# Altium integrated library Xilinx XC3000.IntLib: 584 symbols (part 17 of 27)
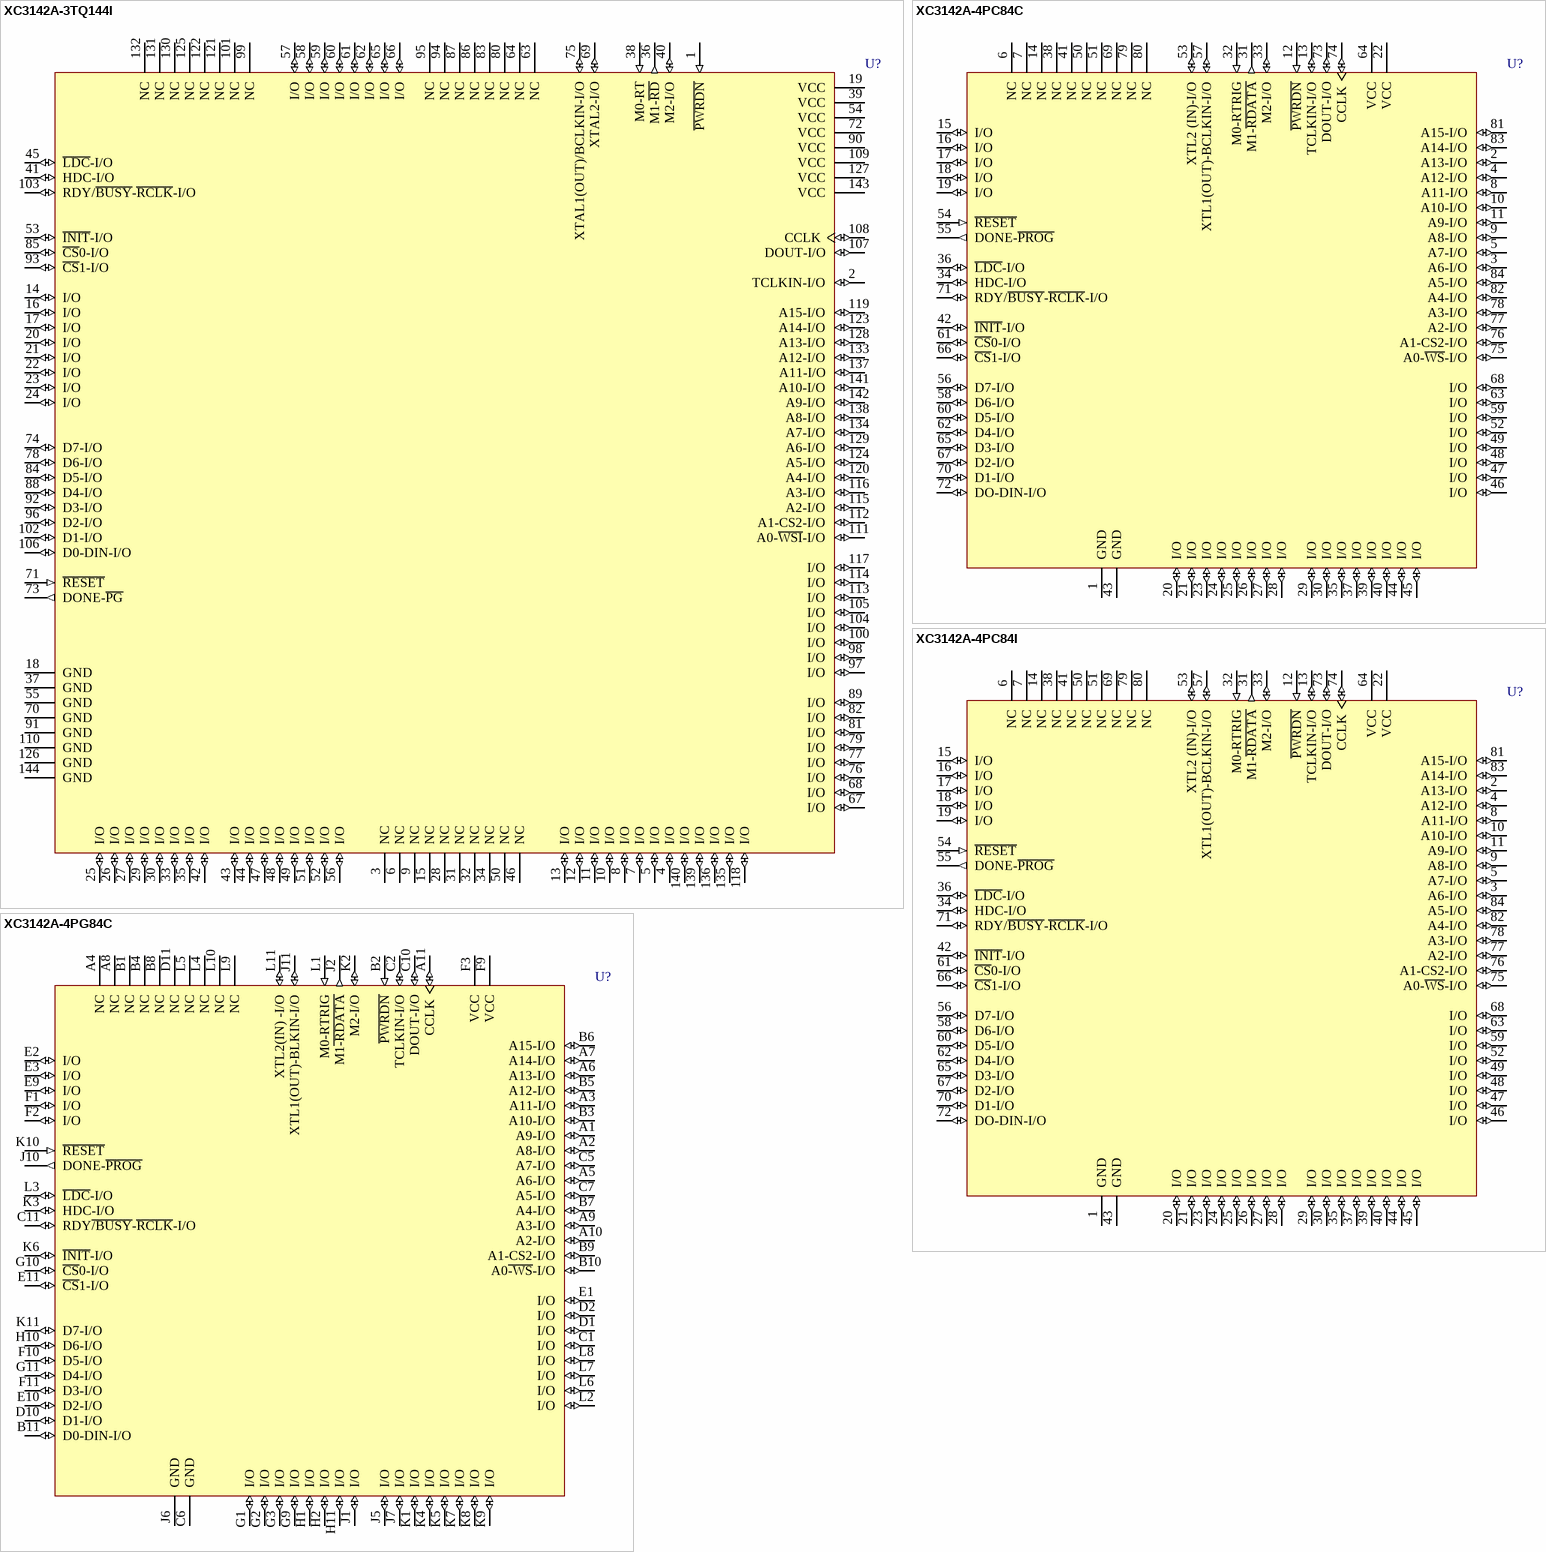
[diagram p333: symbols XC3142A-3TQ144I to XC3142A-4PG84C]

## XC3142A-3TQ144I
designator U?
Logic Cell Array with 144 CLBs, with 96 I/O Pins, 144-Pin TQFP, Industrial Grade; ComponentAvailability: Not for New Design
footprint TQ144_N (Thin QFP, 144-Leads, Body 20x20mm, Pitch 0.5mm, IPC Medium Density)
footprint TQ144_L (Thin QFP, 144-Leads, Body 20x20mm, Pitch 0.5mm, IPC High Density)
footprint TQ144_M (Thin QFP, 144-Leads, Body 20x20mm, Pitch 0.5mm, IPC Low Density)
3D model XC3142A-TQ144 (144-Pin Thin Quad Flat Pack (TQ144))
pins: 1 ~{PWRDN} (in), 2 TCLKIN-I/O (io), 3 NC, 4 I/O (io), 5 I/O (io), 6 NC, 7 I/O (io), 8 I/O (io), 9 NC, 10 I/O (io), 11 I/O (io), 12 I/O (io), 13 I/O (io), 14 I/O (io), 15 NC, 16 I/O (io), 17 I/O (io), 18 GND (power), 19 VCC (power), 20 I/O (io), 21 I/O (io), 22 I/O (io), 23 I/O (io), 24 I/O (io), 25 I/O (io), 26 I/O (io), 27 I/O (io), 28 NC, 29 I/O (io), 30 I/O (io), 31 NC, 32 NC, 33 I/O (io), 34 NC, 35 I/O (io), 36 M1-~{RD} (out), 37 GND (power), 38 M0-RT (in), 39 VCC (power), 40 M2-I/O (io), 41 HDC-I/O (io), 42 I/O (io), 43 I/O (io), 44 I/O (io), 45 ~{LDC}-I/O (io), 46 NC, 47 I/O (io), 48 I/O (io), 49 I/O (io), 50 NC, 51 I/O (io), 52 I/O (io), 53 ~{INIT}-I/O (io), 54 VCC (power), 55 GND (power), 56 I/O (io), 57 I/O (io), 58 I/O (io), 59 I/O (io), 60 I/O (io), 61 I/O (io), 62 I/O (io), 63 NC, 64 NC, 65 I/O (io), 66 I/O (io), 67 I/O (io), 68 I/O (io), 69 XTAL2-I/O (io), 70 GND (power), 71 ~{RESET} (in), 72 VCC (power), 73 DONE-~{PG} (out), 74 D7-I/O (io), 75 XTAL1(OUT)/BCLKIN-I/O (io), 76 I/O (io), 77 I/O (io), 78 D6-I/O (io), 79 I/O (io), 80 NC, 81 I/O (io), 82 I/O (io), 83 NC, 84 D5-I/O (io), 85 ~{CS}0-I/O (io), 86 NC, 87 NC, 88 D4-I/O (io), 89 I/O (io), 90 VCC (power), 91 GND (power), 92 D3-I/O (io), 93 ~{CS}1-I/O (io), 94 NC, 95 NC, 96 D2-I/O (io), 97 I/O (io), 98 I/O (io), 99 NC, 100 I/O (io), 101 NC, 102 D1-I/O (io), 103 RDY/~{BUSY}-~{RCLK}-I/O (io), 104 I/O (io), 105 I/O (io), 106 D0-DIN-I/O (io), 107 DOUT-I/O (io), 108 CCLK (io), 109 VCC (power), 110 GND (power), 111 A0-~{WSI}-I/O (io), 112 A1-CS2-I/O (io), 113 I/O (io), 114 I/O (io), 115 A2-I/O (io), 116 A3-I/O (io), 117 I/O (io), 118 I/O (io), 119 A15-I/O (io), 120 A4-I/O (io), 121 NC, 122 NC, 123 A14-I/O (io), 124 A5-I/O (io), 125 NC, 126 GND (power), 127 VCC (power), 128 A13-I/O (io), 129 A6-I/O (io), 130 NC, 131 NC, 132 NC, 133 A12-I/O (io), 134 A7-I/O (io), 135 I/O (io), 136 I/O (io), 137 A11-I/O (io), 138 A8-I/O (io), 139 I/O (io), 140 I/O (io), 141 A10-I/O (io), 142 A9-I/O (io), 143 VCC (power), 144 GND (power)

## XC3142A-4PC84C
designator U?
Logic Cell Array with 144 CLBs, with 64 I/O Pins, 84-Pin PLCC, Commercial Grade; ComponentAvailability: Not for New Design
footprint PC84_N (Leaded Chip Carrier, 84-Leads, Body 29.3x29.3mm, Pitch 1.27mm, IPC Medium Density)
footprint PC84_L (Leaded Chip Carrier, 84-Leads, Body 29.3x29.3mm, Pitch 1.27mm, IPC High Density)
footprint PC84_M (Leaded Chip Carrier, 84-Leads, Body 29.3x29.3mm, Pitch 1.27mm, IPC Low Density)
3D model XC3142A-PC84 (84-Pin Plastic Leaded Chip Carrier (PC84))
pins: 1 GND (power), 2 A13-I/O (io), 3 A6-I/O (io), 4 A12-I/O (io), 5 A7-I/O (io), 6 NC, 7 NC, 8 A11-I/O (io), 9 A8-I/O (io), 10 A10-I/O (io), 11 A9-I/O (io), 12 ~{PWRDN} (in), 13 TCLKIN-I/O (io), 14 NC, 15 I/O (io), 16 I/O (io), 17 I/O (io), 18 I/O (io), 19 I/O (io), 20 I/O (io), 21 I/O (io), 22 VCC (power), 23 I/O (io), 24 I/O (io), 25 I/O (io), 26 I/O (io), 27 I/O (io), 28 I/O (io), 29 I/O (io), 30 I/O (io), 31 M1-~{RDATA} (out), 32 M0-RTRIG (in), 33 M2-I/O (io), 34 HDC-I/O (io), 35 I/O (io), 36 ~{LDC}-I/O (io), 37 I/O (io), 38 NC, 39 I/O (io), 40 I/O (io), 41 NC, 42 ~{INIT}-I/O (io), 43 GND (power), 44 I/O (io), 45 I/O (io), 46 I/O (io), 47 I/O (io), 48 I/O (io), 49 I/O (io), 50 NC, 51 NC, 52 I/O (io), 53 XTL2 (IN)-I/O (io), 54 ~{RESET} (in), 55 DONE-~{PROG} (out), 56 D7-I/O (io), 57 XTL1(OUT)-BCLKIN-I/O (io), 58 D6-I/O (io), 59 I/O (io), 60 D5-I/O (io), 61 ~{CS}0-I/O (io), 62 D4-I/O (io), 63 I/O (io), 64 VCC (power), 65 D3-I/O (io), 66 ~{CS}1-I/O (io), 67 D2-I/O (io), 68 I/O (io), 69 NC, 70 D1-I/O (io), 71 RDY/~{BUSY}-~{RCLK}-I/O (io), 72 DO-DIN-I/O (io), 73 DOUT-I/O (io), 74 CCLK (io), 75 A0-~{WS}-I/O (io), 76 A1-CS2-I/O (io), 77 A2-I/O (io), 78 A3-I/O (io), 79 NC, 80 NC, 81 A15-I/O (io), 82 A4-I/O (io), 83 A14-I/O (io), 84 A5-I/O (io)

## XC3142A-4PC84I
designator U?
Logic Cell Array with 144 CLBs, with 64 I/O Pins, 84-Pin PLCC, Industrial Grade; ComponentAvailability: Not for New Design
footprint PC84_N (Leaded Chip Carrier, 84-Leads, Body 29.3x29.3mm, Pitch 1.27mm, IPC Medium Density)
footprint PC84_L (Leaded Chip Carrier, 84-Leads, Body 29.3x29.3mm, Pitch 1.27mm, IPC High Density)
footprint PC84_M (Leaded Chip Carrier, 84-Leads, Body 29.3x29.3mm, Pitch 1.27mm, IPC Low Density)
3D model XC3142A-PC84 (84-Pin Plastic Leaded Chip Carrier (PC84))
pins: 1 GND (power), 2 A13-I/O (io), 3 A6-I/O (io), 4 A12-I/O (io), 5 A7-I/O (io), 6 NC, 7 NC, 8 A11-I/O (io), 9 A8-I/O (io), 10 A10-I/O (io), 11 A9-I/O (io), 12 ~{PWRDN} (in), 13 TCLKIN-I/O (io), 14 NC, 15 I/O (io), 16 I/O (io), 17 I/O (io), 18 I/O (io), 19 I/O (io), 20 I/O (io), 21 I/O (io), 22 VCC (power), 23 I/O (io), 24 I/O (io), 25 I/O (io), 26 I/O (io), 27 I/O (io), 28 I/O (io), 29 I/O (io), 30 I/O (io), 31 M1-~{RDATA} (out), 32 M0-RTRIG (in), 33 M2-I/O (io), 34 HDC-I/O (io), 35 I/O (io), 36 ~{LDC}-I/O (io), 37 I/O (io), 38 NC, 39 I/O (io), 40 I/O (io), 41 NC, 42 ~{INIT}-I/O (io), 43 GND (power), 44 I/O (io), 45 I/O (io), 46 I/O (io), 47 I/O (io), 48 I/O (io), 49 I/O (io), 50 NC, 51 NC, 52 I/O (io), 53 XTL2 (IN)-I/O (io), 54 ~{RESET} (in), 55 DONE-~{PROG} (out), 56 D7-I/O (io), 57 XTL1(OUT)-BCLKIN-I/O (io), 58 D6-I/O (io), 59 I/O (io), 60 D5-I/O (io), 61 ~{CS}0-I/O (io), 62 D4-I/O (io), 63 I/O (io), 64 VCC (power), 65 D3-I/O (io), 66 ~{CS}1-I/O (io), 67 D2-I/O (io), 68 I/O (io), 69 NC, 70 D1-I/O (io), 71 RDY/~{BUSY}-~{RCLK}-I/O (io), 72 DO-DIN-I/O (io), 73 DOUT-I/O (io), 74 CCLK (io), 75 A0-~{WS}-I/O (io), 76 A1-CS2-I/O (io), 77 A2-I/O (io), 78 A3-I/O (io), 79 NC, 80 NC, 81 A15-I/O (io), 82 A4-I/O (io), 83 A14-I/O (io), 84 A5-I/O (io)

## XC3142A-4PG84C
designator U?
Logic Cell Array with 144 CLBs, with 64 I/O Pins, 84-Pin PGA, Commercial Grade; ComponentAvailability: Not for New Design
footprint PG84 (PGA, 85-Leads, Body 28x28mm, Pitch 2.54mm)
3D model XC3142A-PG84 (84-Pin Ceramic Pin Grid Array (PG84))
pins: A1 A9-I/O (io), A2 A8-I/O (io), A3 A11-I/O (io), A4 NC, A5 A6-I/O (io), A6 A13-I/O (io), A7 A14-I/O (io), A8 NC, A9 A3-I/O (io), A10 A2-I/O (io), A11 CCLK (io), B1 NC, B2 ~{PWRDN} (in), B3 A10-I/O (io), B4 NC, B5 A12-I/O (io), B6 A15-I/O (io), B7 A4-I/O (io), B8 NC, B9 A1-CS2-I/O (io), B10 A0~{-WS}-I/O (io), B11 D0-DIN-I/O (io), C1 I/O (io), C2 TCLKIN-I/O (io), C5 A7-I/O (io), C6 GND (power), C7 A5-I/O (io), C10 DOUT-I/O (io), C11 RDY~{/BUSY}-~{RCLK}-I/O (io), D1 I/O (io), D2 I/O (io), D10 D1-I/O (io), D11 NC, E1 I/O (io), E2 I/O (io), E3 I/O (io), E9 I/O (io), E10 D2-I/O (io), E11 ~{CS}1-I/O (io), F1 I/O (io), F2 I/O (io), F3 VCC (power), F9 VCC (power), F10 D5-I/O (io), F11 D3-I/O (io), G1 I/O (io), G2 I/O (io), G3 I/O (io), G9 I/O (io), G10 ~{CS}0-I/O (io), G11 D4-I/O (io), H1 I/O (io), H2 I/O (io), H10 D6-I/O (io), H11 I/O (io), J1 I/O (io), J2 M1~{-RDATA} (out), J5 I/O (io), J6 GND (power), J7 I/O (io), J10 DONE-~{PROG} (out), J11 XTL1(OUT)-BLKIN-I/O (io), K1 I/O (io), K2 M2-I/O (io), K3 HDC-I/O (io), K4 I/O (io), K5 I/O (io), K6 ~{INIT}-I/O (io), K7 I/O (io), K8 I/O (io), K9 I/O (io), K10 ~{RESET} (in), K11 D7-I/O (io), L1 M0-RTRIG (in), L2 I/O (io), L3 ~{LDC}-I/O (io), L4 NC, L5 NC, L6 I/O (io), L7 I/O (io), L8 I/O (io), L9 NC, L10 NC, L11 XTL2(IN) -I/O (io)

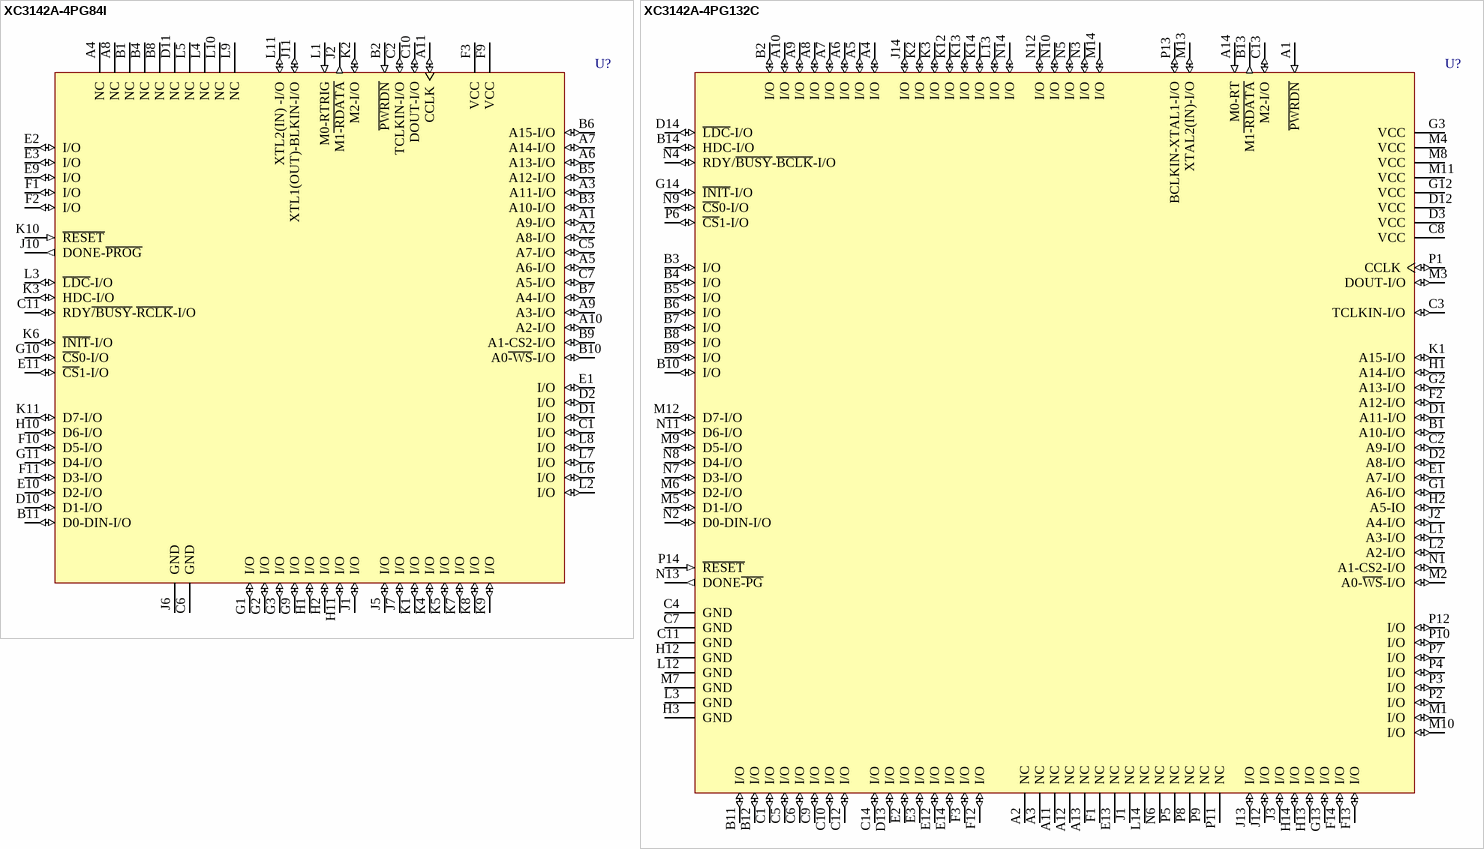
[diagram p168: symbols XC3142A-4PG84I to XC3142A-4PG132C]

## XC3142A-4PG84I
designator U?
Logic Cell Array with 144 CLBs, with 64 I/O Pins, 84-Pin PGA, Industrial Grade; ComponentAvailability: Not for New Design
footprint PG84 (PGA, 85-Leads, Body 28x28mm, Pitch 2.54mm)
3D model XC3142A-PG84 (84-Pin Ceramic Pin Grid Array (PG84))
pins: A1 A9-I/O (io), A2 A8-I/O (io), A3 A11-I/O (io), A4 NC, A5 A6-I/O (io), A6 A13-I/O (io), A7 A14-I/O (io), A8 NC, A9 A3-I/O (io), A10 A2-I/O (io), A11 CCLK (io), B1 NC, B2 ~{PWRDN} (in), B3 A10-I/O (io), B4 NC, B5 A12-I/O (io), B6 A15-I/O (io), B7 A4-I/O (io), B8 NC, B9 A1-CS2-I/O (io), B10 A0~{-WS}-I/O (io), B11 D0-DIN-I/O (io), C1 I/O (io), C2 TCLKIN-I/O (io), C5 A7-I/O (io), C6 GND (power), C7 A5-I/O (io), C10 DOUT-I/O (io), C11 RDY~{/BUSY}-~{RCLK}-I/O (io), D1 I/O (io), D2 I/O (io), D10 D1-I/O (io), D11 NC, E1 I/O (io), E2 I/O (io), E3 I/O (io), E9 I/O (io), E10 D2-I/O (io), E11 ~{CS}1-I/O (io), F1 I/O (io), F2 I/O (io), F3 VCC (power), F9 VCC (power), F10 D5-I/O (io), F11 D3-I/O (io), G1 I/O (io), G2 I/O (io), G3 I/O (io), G9 I/O (io), G10 ~{CS}0-I/O (io), G11 D4-I/O (io), H1 I/O (io), H2 I/O (io), H10 D6-I/O (io), H11 I/O (io), J1 I/O (io), J2 M1~{-RDATA} (out), J5 I/O (io), J6 GND (power), J7 I/O (io), J10 DONE-~{PROG} (out), J11 XTL1(OUT)-BLKIN-I/O (io), K1 I/O (io), K2 M2-I/O (io), K3 HDC-I/O (io), K4 I/O (io), K5 I/O (io), K6 ~{INIT}-I/O (io), K7 I/O (io), K8 I/O (io), K9 I/O (io), K10 ~{RESET} (in), K11 D7-I/O (io), L1 M0-RTRIG (in), L2 I/O (io), L3 ~{LDC}-I/O (io), L4 NC, L5 NC, L6 I/O (io), L7 I/O (io), L8 I/O (io), L9 NC, L10 NC, L11 XTL2(IN) -I/O (io)

## XC3142A-4PG132C
designator U?
Logic Cell Array with 144 CLBs, with 96 I/O Pins, 132-Pin PGA, Commercial Grade; ComponentAvailability: Not for New Design
footprint PG132 (PGA, 132-Leads, Body 37x37mm, Pitch 2.54mm)
3D model XC3142A-PG132 (132-Pin Ceramic Pin Grid Array (PG132))
pins: A1 ~{PWRDN} (in), A2 NC, A3 NC, A4 I/O (io), A5 I/O (io), A6 I/O (io), A7 I/O (io), A8 I/O (io), A9 I/O (io), A10 I/O (io), A11 NC, A12 NC, A13 NC, A14 M0-RT (in), B1 A10-I/O (io), B2 I/O (io), B3 I/O (io), B4 I/O (io), B5 I/O (io), B6 I/O (io), B7 I/O (io), B8 I/O (io), B9 I/O (io), B10 I/O (io), B11 I/O (io), B12 I/O (io), B13 M1~{-RDATA} (out), B14 HDC-I/O (io), C1 I/O (io), C2 A9-I/O (io), C3 TCLKIN-I/O (io), C4 GND (power), C5 I/O (io), C6 I/O (io), C7 GND (power), C8 VCC (power), C9 I/O (io), C10 I/O (io), C11 GND (power), C12 I/O (io), C13 M2-I/O (io), C14 I/O (io), D1 A11-I/O (io), D2 A8-I/O (io), D3 VCC (power), D12 VCC (power), D13 I/O (io), D14 ~{LDC}-I/O (io), E1 A7-I/O (io), E2 I/O (io), E3 I/O (io), E12 I/O (io), E13 NC, E14 I/O (io), F1 NC, F2 A12-I/O (io), F3 I/O (io), F12 I/O (io), F13 I/O (io), F14 I/O (io), G1 A6-I/O (io), G2 A13-I/O (io), G3 VCC (power), G12 VCC (power), G13 I/O (io), G14 ~{INIT}-I/O (io), H1 A14-I/O (io), H2 A5-IO (io), H3 GND (power), H12 GND (power), H13 I/O (io), H14 I/O (io), J1 NC, J2 A4-I/O (io), J3 I/O (io), J12 I/O (io), J13 I/O (io), J14 I/O (io), K1 A15-I/O (io), K2 I/O (io), K3 I/O (io), K12 I/O (io), K13 I/O (io), K14 I/O (io), L1 A3-I/O (io), L2 A2-I/O (io), L3 GND (power), L12 GND (power), L13 I/O (io), L14 NC, M1 I/O (io), M2 A0-~{WS}-I/O (io), M3 DOUT-I/O (io), M4 VCC (power), M5 D1-I/O (io), M6 D2-I/O (io), M7 GND (power), M8 VCC (power), M9 D5-I/O (io), M10 I/O (io), M11 VCC (power), M12 D7-I/O (io), M13 XTAL2(IN)-I/O (io), M14 I/O (io), N1 A1-CS2-I/O (io), N2 D0-DIN-I/O (io), N3 I/O (io), N4 RDY/~{BUSY}-~{BCLK}-I/O (io), N5 I/O (io), N6 NC, N7 D3-I/O (io), N8 D4-I/O (io), N9 ~{CS}0-I/O (io), N10 I/O (io), N11 D6-I/O (io), N12 I/O (io), N13 DONE~{-PG} (out), N14 I/O (io), P1 CCLK (io), P2 I/O (io), P3 I/O (io), P4 I/O (io), P5 NC, P6 ~{CS}1-I/O (io), P7 I/O (io), P8 NC, P9 NC, P10 I/O (io), P11 NC, P12 I/O (io), P13 BCLKIN-XTAL1-I/O (io), P14 ~{RESET} (in)

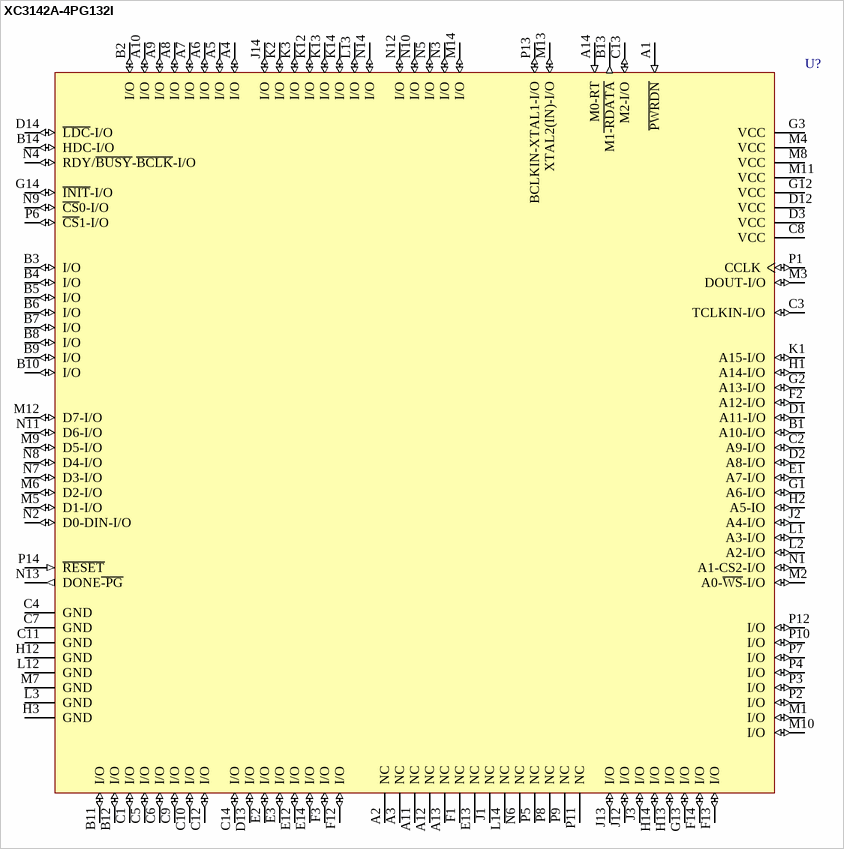
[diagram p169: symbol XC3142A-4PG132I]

## XC3142A-4PG132I
designator U?
Logic Cell Array with 144 CLBs, with 96 I/O Pins, 132-Pin PGA, Industrial Grade; ComponentAvailability: Not for New Design
footprint PG132 (PGA, 132-Leads, Body 37x37mm, Pitch 2.54mm)
3D model XC3142A-PG132 (132-Pin Ceramic Pin Grid Array (PG132))
pins: A1 ~{PWRDN} (in), A2 NC, A3 NC, A4 I/O (io), A5 I/O (io), A6 I/O (io), A7 I/O (io), A8 I/O (io), A9 I/O (io), A10 I/O (io), A11 NC, A12 NC, A13 NC, A14 M0-RT (in), B1 A10-I/O (io), B2 I/O (io), B3 I/O (io), B4 I/O (io), B5 I/O (io), B6 I/O (io), B7 I/O (io), B8 I/O (io), B9 I/O (io), B10 I/O (io), B11 I/O (io), B12 I/O (io), B13 M1~{-RDATA} (out), B14 HDC-I/O (io), C1 I/O (io), C2 A9-I/O (io), C3 TCLKIN-I/O (io), C4 GND (power), C5 I/O (io), C6 I/O (io), C7 GND (power), C8 VCC (power), C9 I/O (io), C10 I/O (io), C11 GND (power), C12 I/O (io), C13 M2-I/O (io), C14 I/O (io), D1 A11-I/O (io), D2 A8-I/O (io), D3 VCC (power), D12 VCC (power), D13 I/O (io), D14 ~{LDC}-I/O (io), E1 A7-I/O (io), E2 I/O (io), E3 I/O (io), E12 I/O (io), E13 NC, E14 I/O (io), F1 NC, F2 A12-I/O (io), F3 I/O (io), F12 I/O (io), F13 I/O (io), F14 I/O (io), G1 A6-I/O (io), G2 A13-I/O (io), G3 VCC (power), G12 VCC (power), G13 I/O (io), G14 ~{INIT}-I/O (io), H1 A14-I/O (io), H2 A5-IO (io), H3 GND (power), H12 GND (power), H13 I/O (io), H14 I/O (io), J1 NC, J2 A4-I/O (io), J3 I/O (io), J12 I/O (io), J13 I/O (io), J14 I/O (io), K1 A15-I/O (io), K2 I/O (io), K3 I/O (io), K12 I/O (io), K13 I/O (io), K14 I/O (io), L1 A3-I/O (io), L2 A2-I/O (io), L3 GND (power), L12 GND (power), L13 I/O (io), L14 NC, M1 I/O (io), M2 A0-~{WS}-I/O (io), M3 DOUT-I/O (io), M4 VCC (power), M5 D1-I/O (io), M6 D2-I/O (io), M7 GND (power), M8 VCC (power), M9 D5-I/O (io), M10 I/O (io), M11 VCC (power), M12 D7-I/O (io), M13 XTAL2(IN)-I/O (io), M14 I/O (io), N1 A1-CS2-I/O (io), N2 D0-DIN-I/O (io), N3 I/O (io), N4 RDY/~{BUSY}-~{BCLK}-I/O (io), N5 I/O (io), N6 NC, N7 D3-I/O (io), N8 D4-I/O (io), N9 ~{CS}0-I/O (io), N10 I/O (io), N11 D6-I/O (io), N12 I/O (io), N13 DONE~{-PG} (out), N14 I/O (io), P1 CCLK (io), P2 I/O (io), P3 I/O (io), P4 I/O (io), P5 NC, P6 ~{CS}1-I/O (io), P7 I/O (io), P8 NC, P9 NC, P10 I/O (io), P11 NC, P12 I/O (io), P13 BCLKIN-XTAL1-I/O (io), P14 ~{RESET} (in)

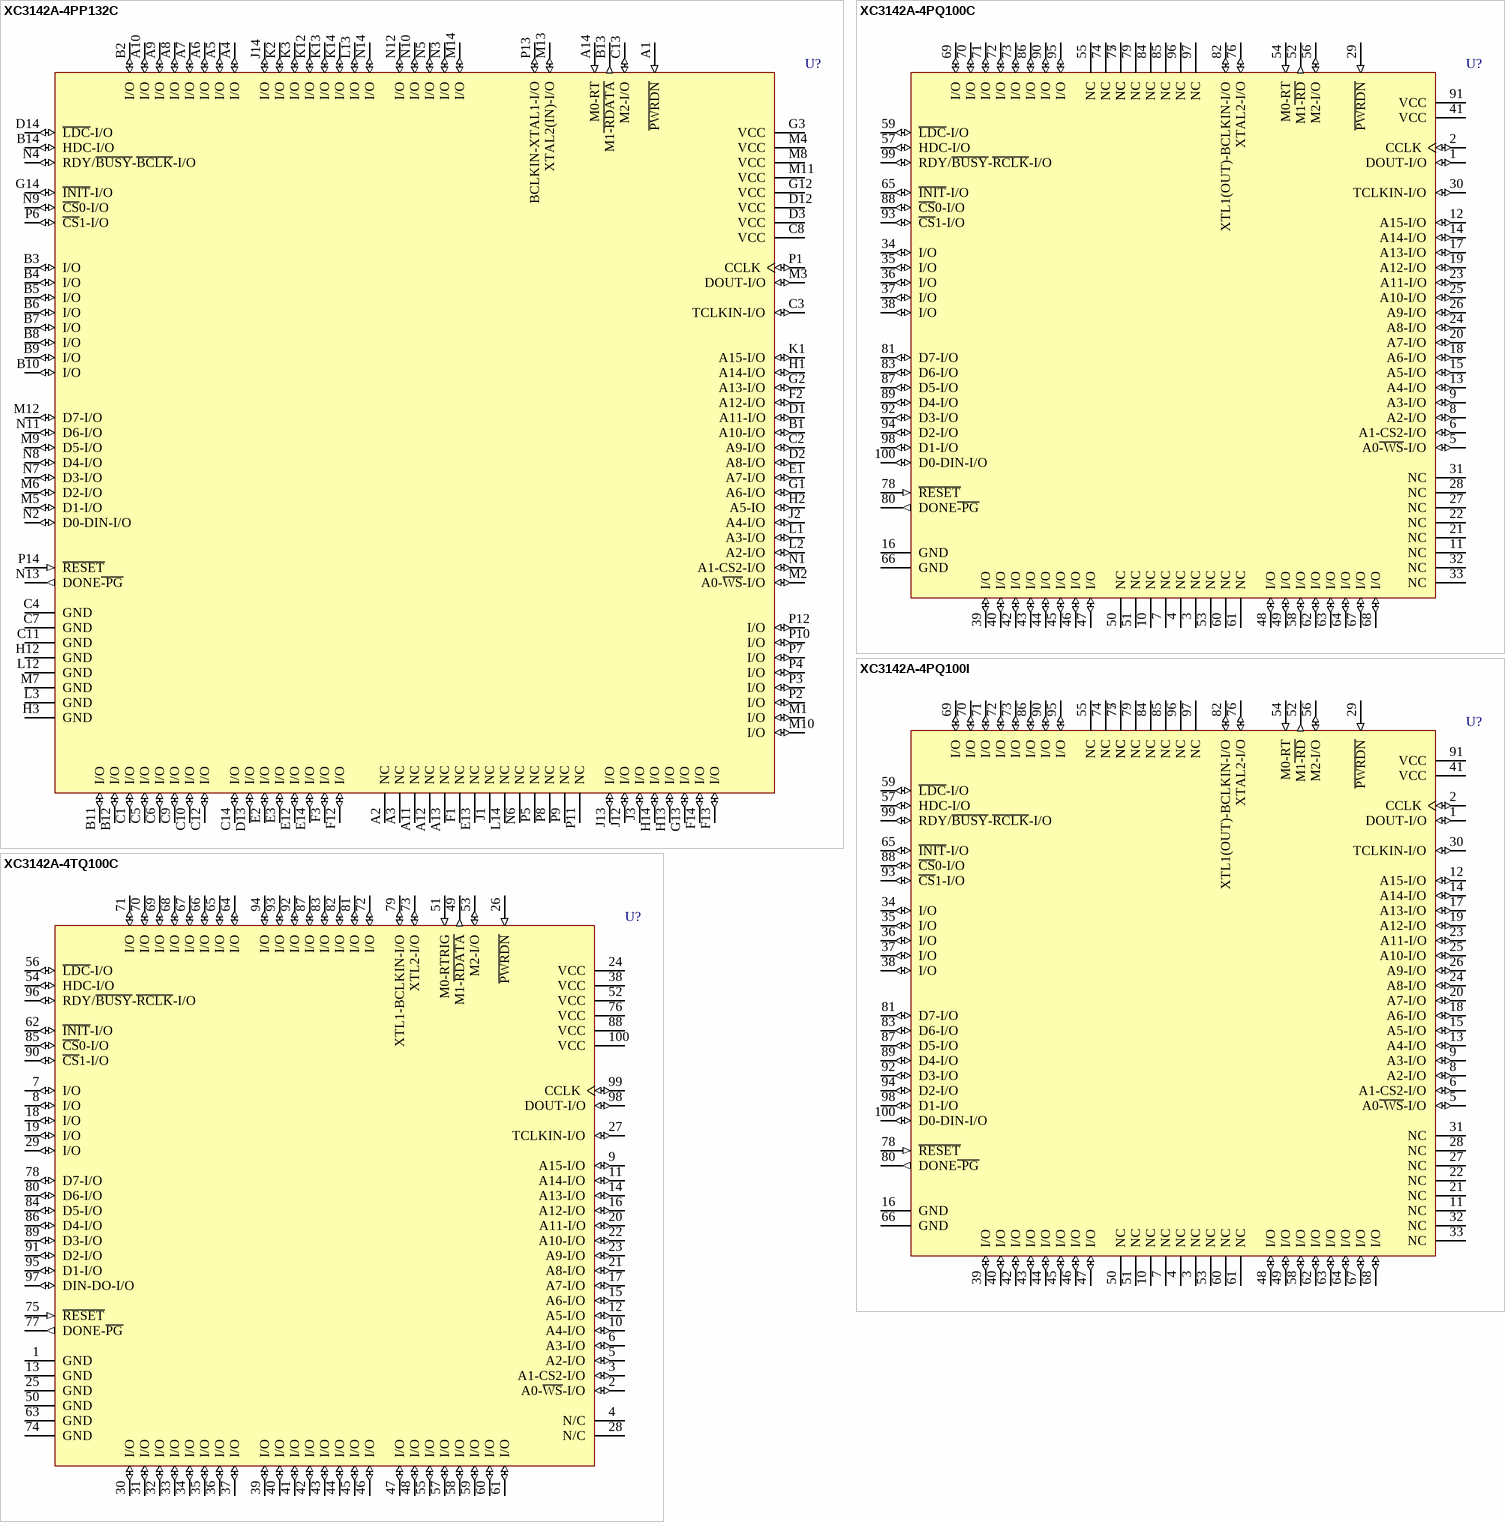
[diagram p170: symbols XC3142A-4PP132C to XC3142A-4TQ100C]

## XC3142A-4PP132C
designator U?
Logic Cell Array with 144 CLBs, with 96 I/O Pins, 132-Pin PGA, Commercial Grade; ComponentAvailability: Not for New Design
footprint PP132 (PGA, 132-Leads, Body 37x37mm, Pitch 2.54mm)
3D model XC3142A-PP132 (132-Pin Plastic Pin Grid Array (PP132))
pins: A1 ~{PWRDN} (in), A2 NC, A3 NC, A4 I/O (io), A5 I/O (io), A6 I/O (io), A7 I/O (io), A8 I/O (io), A9 I/O (io), A10 I/O (io), A11 NC, A12 NC, A13 NC, A14 M0-RT (in), B1 A10-I/O (io), B2 I/O (io), B3 I/O (io), B4 I/O (io), B5 I/O (io), B6 I/O (io), B7 I/O (io), B8 I/O (io), B9 I/O (io), B10 I/O (io), B11 I/O (io), B12 I/O (io), B13 M1~{-RDATA} (out), B14 HDC-I/O (io), C1 I/O (io), C2 A9-I/O (io), C3 TCLKIN-I/O (io), C4 GND (power), C5 I/O (io), C6 I/O (io), C7 GND (power), C8 VCC (power), C9 I/O (io), C10 I/O (io), C11 GND (power), C12 I/O (io), C13 M2-I/O (io), C14 I/O (io), D1 A11-I/O (io), D2 A8-I/O (io), D3 VCC (power), D12 VCC (power), D13 I/O (io), D14 ~{LDC}-I/O (io), E1 A7-I/O (io), E2 I/O (io), E3 I/O (io), E12 I/O (io), E13 NC, E14 I/O (io), F1 NC, F2 A12-I/O (io), F3 I/O (io), F12 I/O (io), F13 I/O (io), F14 I/O (io), G1 A6-I/O (io), G2 A13-I/O (io), G3 VCC (power), G12 VCC (power), G13 I/O (io), G14 ~{INIT}-I/O (io), H1 A14-I/O (io), H2 A5-IO (io), H3 GND (power), H12 GND (power), H13 I/O (io), H14 I/O (io), J1 NC, J2 A4-I/O (io), J3 I/O (io), J12 I/O (io), J13 I/O (io), J14 I/O (io), K1 A15-I/O (io), K2 I/O (io), K3 I/O (io), K12 I/O (io), K13 I/O (io), K14 I/O (io), L1 A3-I/O (io), L2 A2-I/O (io), L3 GND (power), L12 GND (power), L13 I/O (io), L14 NC, M1 I/O (io), M2 A0-~{WS}-I/O (io), M3 DOUT-I/O (io), M4 VCC (power), M5 D1-I/O (io), M6 D2-I/O (io), M7 GND (power), M8 VCC (power), M9 D5-I/O (io), M10 I/O (io), M11 VCC (power), M12 D7-I/O (io), M13 XTAL2(IN)-I/O (io), M14 I/O (io), N1 A1-CS2-I/O (io), N2 D0-DIN-I/O (io), N3 I/O (io), N4 RDY/~{BUSY}-~{BCLK}-I/O (io), N5 I/O (io), N6 NC, N7 D3-I/O (io), N8 D4-I/O (io), N9 ~{CS}0-I/O (io), N10 I/O (io), N11 D6-I/O (io), N12 I/O (io), N13 DONE~{-PG} (out), N14 I/O (io), P1 CCLK (io), P2 I/O (io), P3 I/O (io), P4 I/O (io), P5 NC, P6 ~{CS}1-I/O (io), P7 I/O (io), P8 NC, P9 NC, P10 I/O (io), P11 NC, P12 I/O (io), P13 BCLKIN-XTAL1-I/O (io), P14 ~{RESET} (in)

## XC3142A-4PQ100C
designator U?
Logic Cell Array with 144 CLBs, with 62 I/O Pins, 100-Pin PQFP, Commercial Grade; ComponentAvailability: Not for New Design
footprint PQ100_N (QFP, 100-Leads, Body 20x14mm, Pitch 0.65mm, IPC Medium Density)
footprint PQ100_L (QFP, 100-Leads, Body 20x14mm, Pitch 0.65mm, IPC High Density)
footprint PQ100_M (QFP, 100-Leads, Body 20x14mm, Pitch 0.65mm, IPC Low Density)
3D model XC3142A-PQ100 (100-Pin Plastic Quad Flat Pack (PQ100))
pins: 1 DOUT-I/O (io), 2 CCLK (io), 3 NC, 4 NC, 5 A0~{-WS}-I/O (io), 6 A1-CS2-I/O (io), 7 NC, 8 A2-I/O (io), 9 A3-I/O (io), 10 NC, 11 NC, 12 A15-I/O (io), 13 A4-I/O (io), 14 A14-I/O (io), 15 A5-I/O (io), 16 GND (power), 17 A13-I/O (io), 18 A6-I/O (io), 19 A12-I/O (io), 20 A7-I/O (io), 21 NC, 22 NC, 23 A11-I/O (io), 24 A8-I/O (io), 25 A10-I/O (io), 26 A9-I/O (io), 27 NC, 28 NC, 29 ~{PWRDN} (in), 30 TCLKIN-I/O (io), 31 NC, 32 NC, 33 NC, 34 I/O (io), 35 I/O (io), 36 I/O (io), 37 I/O (io), 38 I/O (io), 39 I/O (io), 40 I/O (io), 41 VCC (power), 42 I/O (io), 43 I/O (io), 44 I/O (io), 45 I/O (io), 46 I/O (io), 47 I/O (io), 48 I/O (io), 49 I/O (io), 50 NC, 51 NC, 52 M1~{-RD} (out), 53 NC, 54 M0-RT (in), 55 NC, 56 M2-I/O (io), 57 HDC-I/O (io), 58 I/O (io), 59 ~{LDC}-I/O (io), 60 NC, 61 NC, 62 I/O (io), 63 I/O (io), 64 I/O (io), 65 ~{INIT}-I/O (io), 66 GND (power), 67 I/O (io), 68 I/O (io), 69 I/O (io), 70 I/O (io), 71 I/O (io), 72 I/O (io), 73 I/O (io), 74 NC, 75 NC, 76 XTAL2-I/O (io), 77 NC, 78 ~{RESET} (in), 79 NC, 80 DONE~{-PG} (out), 81 D7-I/O (io), 82 XTL1(OUT)-BCLKIN-I/O (io), 83 D6-I/O (io), 84 NC, 85 NC, 86 I/O (io), 87 D5-I/O (io), 88 ~{CS}0-I/O (io), 89 D4-I/O (io), 90 I/O (io), 91 VCC (power), 92 D3-I/O (io), 93 ~{CS}1-I/O (io), 94 D2-I/O (io), 95 I/O (io), 96 NC, 97 NC, 98 D1-I/O (io), 99 RDY/~{BUSY}-~{RCLK}-I/O (io), 100 D0-DIN-I/O (io)

## XC3142A-4PQ100I
designator U?
Logic Cell Array with 144 CLBs, with 62 I/O Pins, 100-Pin PQFP, Industrial Grade; ComponentAvailability: Not for New Design
footprint PQ100_N (QFP, 100-Leads, Body 20x14mm, Pitch 0.65mm, IPC Medium Density)
footprint PQ100_L (QFP, 100-Leads, Body 20x14mm, Pitch 0.65mm, IPC High Density)
footprint PQ100_M (QFP, 100-Leads, Body 20x14mm, Pitch 0.65mm, IPC Low Density)
3D model XC3142A-PQ100 (100-Pin Plastic Quad Flat Pack (PQ100))
pins: 1 DOUT-I/O (io), 2 CCLK (io), 3 NC, 4 NC, 5 A0~{-WS}-I/O (io), 6 A1-CS2-I/O (io), 7 NC, 8 A2-I/O (io), 9 A3-I/O (io), 10 NC, 11 NC, 12 A15-I/O (io), 13 A4-I/O (io), 14 A14-I/O (io), 15 A5-I/O (io), 16 GND (power), 17 A13-I/O (io), 18 A6-I/O (io), 19 A12-I/O (io), 20 A7-I/O (io), 21 NC, 22 NC, 23 A11-I/O (io), 24 A8-I/O (io), 25 A10-I/O (io), 26 A9-I/O (io), 27 NC, 28 NC, 29 ~{PWRDN} (in), 30 TCLKIN-I/O (io), 31 NC, 32 NC, 33 NC, 34 I/O (io), 35 I/O (io), 36 I/O (io), 37 I/O (io), 38 I/O (io), 39 I/O (io), 40 I/O (io), 41 VCC (power), 42 I/O (io), 43 I/O (io), 44 I/O (io), 45 I/O (io), 46 I/O (io), 47 I/O (io), 48 I/O (io), 49 I/O (io), 50 NC, 51 NC, 52 M1~{-RD} (out), 53 NC, 54 M0-RT (in), 55 NC, 56 M2-I/O (io), 57 HDC-I/O (io), 58 I/O (io), 59 ~{LDC}-I/O (io), 60 NC, 61 NC, 62 I/O (io), 63 I/O (io), 64 I/O (io), 65 ~{INIT}-I/O (io), 66 GND (power), 67 I/O (io), 68 I/O (io), 69 I/O (io), 70 I/O (io), 71 I/O (io), 72 I/O (io), 73 I/O (io), 74 NC, 75 NC, 76 XTAL2-I/O (io), 77 NC, 78 ~{RESET} (in), 79 NC, 80 DONE~{-PG} (out), 81 D7-I/O (io), 82 XTL1(OUT)-BCLKIN-I/O (io), 83 D6-I/O (io), 84 NC, 85 NC, 86 I/O (io), 87 D5-I/O (io), 88 ~{CS}0-I/O (io), 89 D4-I/O (io), 90 I/O (io), 91 VCC (power), 92 D3-I/O (io), 93 ~{CS}1-I/O (io), 94 D2-I/O (io), 95 I/O (io), 96 NC, 97 NC, 98 D1-I/O (io), 99 RDY/~{BUSY}-~{RCLK}-I/O (io), 100 D0-DIN-I/O (io)

## XC3142A-4TQ100C
designator U?
Logic Cell Array with 144 CLBs, with 80 I/O Pins, 100-Pin TQFP, Commercial Grade; ComponentAvailability: Not for New Design
footprint TQ100_N (Thin QFP, 100-Leads, Body 14x14mm, Pitch 0.5mm, IPC Medium Density)
footprint TQ100_L (Thin QFP, 100-Leads, Body 14x14mm, Pitch 0.5mm, IPC High Density)
footprint TQ100_M (Thin QFP, 100-Leads, Body 14x14mm, Pitch 0.5mm, IPC Low Density)
3D model XC3142A-TQ100 (100-Pin Thin Quad Flat Pack (TQ100))
pins: 1 GND (power), 2 A0-~{WS}-I/O (io), 3 A1-CS2-I/O (io), 4 N/C, 5 A2-I/O (io), 6 A3-I/O (io), 7 I/O (io), 8 I/O (io), 9 A15-I/O (io), 10 A4-I/O (io), 11 A14-I/O (io), 12 A5-I/O (io), 13 GND (power), 14 A13-I/O (io), 15 A6-I/O (io), 16 A12-I/O (io), 17 A7-I/O (io), 18 I/O (io), 19 I/O (io), 20 A11-I/O (io), 21 A8-I/O (io), 22 A10-I/O (io), 23 A9-I/O (io), 24 VCC (power), 25 GND (power), 26 ~{PWRDN} (in), 27 TCLKIN-I/O (io), 28 N/C, 29 I/O (io), 30 I/O (io), 31 I/O (io), 32 I/O (io), 33 I/O (io), 34 I/O (io), 35 I/O (io), 36 I/O (io), 37 I/O (io), 38 VCC (power), 39 I/O (io), 40 I/O (io), 41 I/O (io), 42 I/O (io), 43 I/O (io), 44 I/O (io), 45 I/O (io), 46 I/O (io), 47 I/O (io), 48 I/O (io), 49 M1-~{RDATA} (out), 50 GND (power), 51 M0-RTRIG (in), 52 VCC (power), 53 M2-I/O (io), 54 HDC-I/O (io), 55 I/O (io), 56 ~{LDC}-I/O (io), 57 I/O (io), 58 I/O (io), 59 I/O (io), 60 I/O (io), 61 I/O (io), 62 ~{INIT}-I/O (io), 63 GND (power), 64 I/O (io), 65 I/O (io), 66 I/O (io), 67 I/O (io), 68 I/O (io), 69 I/O (io), 70 I/O (io), 71 I/O (io), 72 I/O (io), 73 XTL2-I/O (io), 74 GND (power), 75 ~{RESET} (in), 76 VCC (power), 77 DONE-~{PG} (out), 78 D7-I/O (io), 79 XTL1-BCLKIN-I/O (io), 80 D6-I/O (io), 81 I/O (io), 82 I/O (io), 83 I/O (io), 84 D5-I/O (io), 85 ~{CS}0-I/O (io), 86 D4-I/O (io), 87 I/O (io), 88 VCC (power), 89 D3-I/O (io), 90 ~{CS}1-I/O (io), 91 D2-I/O (io), 92 I/O (io), 93 I/O (io), 94 I/O (io), 95 D1-I/O (io), 96 RDY/~{BUSY}-~{RCLK}-I/O (io), 97 DIN-DO-I/O (io), 98 DOUT-I/O (io), 99 CCLK (io), 100 VCC (power)

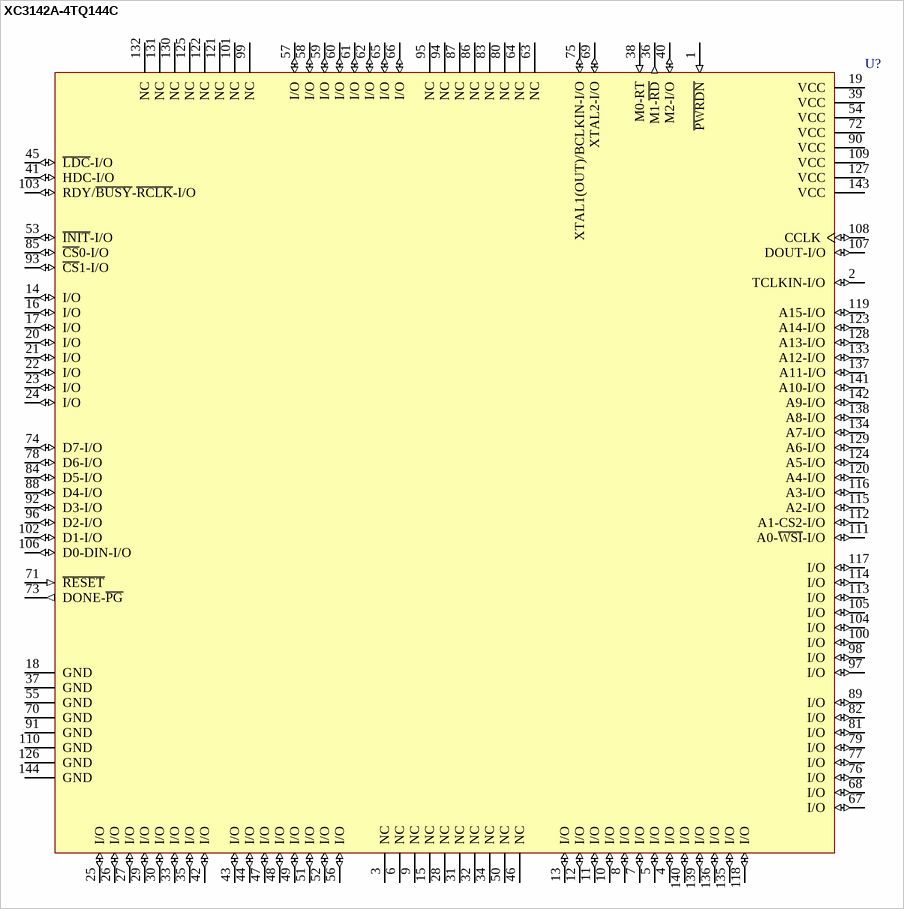
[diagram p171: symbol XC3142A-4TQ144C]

## XC3142A-4TQ144C
designator U?
Logic Cell Array with 144 CLBs, with 96 I/O Pins, 144-Pin TQFP, Commercial Grade; ComponentAvailability: Not for New Design
footprint TQ144_N (Thin QFP, 144-Leads, Body 20x20mm, Pitch 0.5mm, IPC Medium Density)
footprint TQ144_L (Thin QFP, 144-Leads, Body 20x20mm, Pitch 0.5mm, IPC High Density)
footprint TQ144_M (Thin QFP, 144-Leads, Body 20x20mm, Pitch 0.5mm, IPC Low Density)
3D model XC3142A-TQ144 (144-Pin Thin Quad Flat Pack (TQ144))
pins: 1 ~{PWRDN} (in), 2 TCLKIN-I/O (io), 3 NC, 4 I/O (io), 5 I/O (io), 6 NC, 7 I/O (io), 8 I/O (io), 9 NC, 10 I/O (io), 11 I/O (io), 12 I/O (io), 13 I/O (io), 14 I/O (io), 15 NC, 16 I/O (io), 17 I/O (io), 18 GND (power), 19 VCC (power), 20 I/O (io), 21 I/O (io), 22 I/O (io), 23 I/O (io), 24 I/O (io), 25 I/O (io), 26 I/O (io), 27 I/O (io), 28 NC, 29 I/O (io), 30 I/O (io), 31 NC, 32 NC, 33 I/O (io), 34 NC, 35 I/O (io), 36 M1-~{RD} (out), 37 GND (power), 38 M0-RT (in), 39 VCC (power), 40 M2-I/O (io), 41 HDC-I/O (io), 42 I/O (io), 43 I/O (io), 44 I/O (io), 45 ~{LDC}-I/O (io), 46 NC, 47 I/O (io), 48 I/O (io), 49 I/O (io), 50 NC, 51 I/O (io), 52 I/O (io), 53 ~{INIT}-I/O (io), 54 VCC (power), 55 GND (power), 56 I/O (io), 57 I/O (io), 58 I/O (io), 59 I/O (io), 60 I/O (io), 61 I/O (io), 62 I/O (io), 63 NC, 64 NC, 65 I/O (io), 66 I/O (io), 67 I/O (io), 68 I/O (io), 69 XTAL2-I/O (io), 70 GND (power), 71 ~{RESET} (in), 72 VCC (power), 73 DONE-~{PG} (out), 74 D7-I/O (io), 75 XTAL1(OUT)/BCLKIN-I/O (io), 76 I/O (io), 77 I/O (io), 78 D6-I/O (io), 79 I/O (io), 80 NC, 81 I/O (io), 82 I/O (io), 83 NC, 84 D5-I/O (io), 85 ~{CS}0-I/O (io), 86 NC, 87 NC, 88 D4-I/O (io), 89 I/O (io), 90 VCC (power), 91 GND (power), 92 D3-I/O (io), 93 ~{CS}1-I/O (io), 94 NC, 95 NC, 96 D2-I/O (io), 97 I/O (io), 98 I/O (io), 99 NC, 100 I/O (io), 101 NC, 102 D1-I/O (io), 103 RDY/~{BUSY}-~{RCLK}-I/O (io), 104 I/O (io), 105 I/O (io), 106 D0-DIN-I/O (io), 107 DOUT-I/O (io), 108 CCLK (io), 109 VCC (power), 110 GND (power), 111 A0-~{WSI}-I/O (io), 112 A1-CS2-I/O (io), 113 I/O (io), 114 I/O (io), 115 A2-I/O (io), 116 A3-I/O (io), 117 I/O (io), 118 I/O (io), 119 A15-I/O (io), 120 A4-I/O (io), 121 NC, 122 NC, 123 A14-I/O (io), 124 A5-I/O (io), 125 NC, 126 GND (power), 127 VCC (power), 128 A13-I/O (io), 129 A6-I/O (io), 130 NC, 131 NC, 132 NC, 133 A12-I/O (io), 134 A7-I/O (io), 135 I/O (io), 136 I/O (io), 137 A11-I/O (io), 138 A8-I/O (io), 139 I/O (io), 140 I/O (io), 141 A10-I/O (io), 142 A9-I/O (io), 143 VCC (power), 144 GND (power)

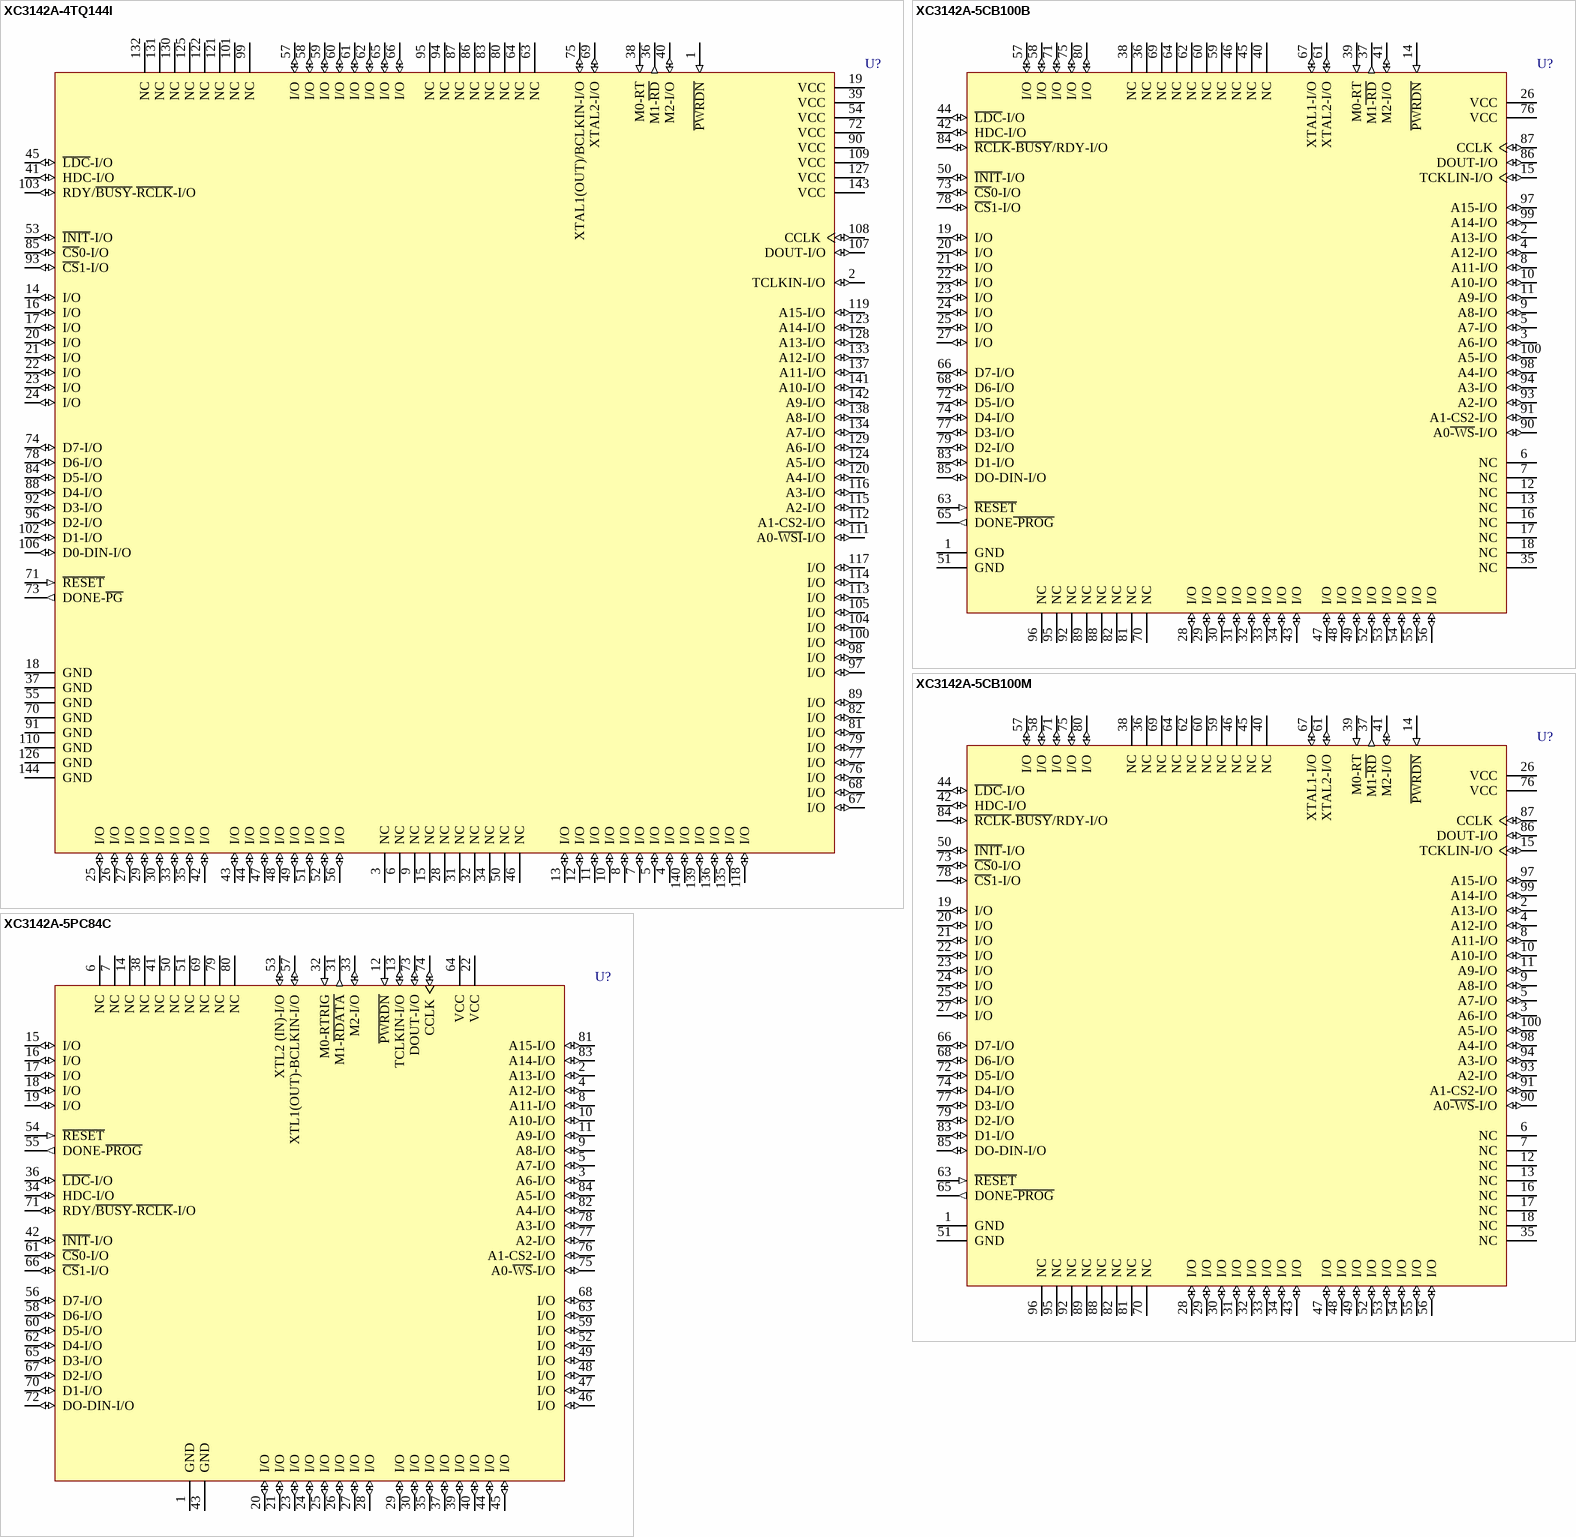
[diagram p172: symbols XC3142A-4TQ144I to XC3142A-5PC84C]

## XC3142A-4TQ144I
designator U?
Logic Cell Array with 144 CLBs, with 96 I/O Pins, 144-Pin TQFP, Industrial Grade; ComponentAvailability: Not for New Design
footprint TQ144_N (Thin QFP, 144-Leads, Body 20x20mm, Pitch 0.5mm, IPC Medium Density)
footprint TQ144_L (Thin QFP, 144-Leads, Body 20x20mm, Pitch 0.5mm, IPC High Density)
footprint TQ144_M (Thin QFP, 144-Leads, Body 20x20mm, Pitch 0.5mm, IPC Low Density)
3D model XC3142A-TQ144 (144-Pin Thin Quad Flat Pack (TQ144))
pins: 1 ~{PWRDN} (in), 2 TCLKIN-I/O (io), 3 NC, 4 I/O (io), 5 I/O (io), 6 NC, 7 I/O (io), 8 I/O (io), 9 NC, 10 I/O (io), 11 I/O (io), 12 I/O (io), 13 I/O (io), 14 I/O (io), 15 NC, 16 I/O (io), 17 I/O (io), 18 GND (power), 19 VCC (power), 20 I/O (io), 21 I/O (io), 22 I/O (io), 23 I/O (io), 24 I/O (io), 25 I/O (io), 26 I/O (io), 27 I/O (io), 28 NC, 29 I/O (io), 30 I/O (io), 31 NC, 32 NC, 33 I/O (io), 34 NC, 35 I/O (io), 36 M1-~{RD} (out), 37 GND (power), 38 M0-RT (in), 39 VCC (power), 40 M2-I/O (io), 41 HDC-I/O (io), 42 I/O (io), 43 I/O (io), 44 I/O (io), 45 ~{LDC}-I/O (io), 46 NC, 47 I/O (io), 48 I/O (io), 49 I/O (io), 50 NC, 51 I/O (io), 52 I/O (io), 53 ~{INIT}-I/O (io), 54 VCC (power), 55 GND (power), 56 I/O (io), 57 I/O (io), 58 I/O (io), 59 I/O (io), 60 I/O (io), 61 I/O (io), 62 I/O (io), 63 NC, 64 NC, 65 I/O (io), 66 I/O (io), 67 I/O (io), 68 I/O (io), 69 XTAL2-I/O (io), 70 GND (power), 71 ~{RESET} (in), 72 VCC (power), 73 DONE-~{PG} (out), 74 D7-I/O (io), 75 XTAL1(OUT)/BCLKIN-I/O (io), 76 I/O (io), 77 I/O (io), 78 D6-I/O (io), 79 I/O (io), 80 NC, 81 I/O (io), 82 I/O (io), 83 NC, 84 D5-I/O (io), 85 ~{CS}0-I/O (io), 86 NC, 87 NC, 88 D4-I/O (io), 89 I/O (io), 90 VCC (power), 91 GND (power), 92 D3-I/O (io), 93 ~{CS}1-I/O (io), 94 NC, 95 NC, 96 D2-I/O (io), 97 I/O (io), 98 I/O (io), 99 NC, 100 I/O (io), 101 NC, 102 D1-I/O (io), 103 RDY/~{BUSY}-~{RCLK}-I/O (io), 104 I/O (io), 105 I/O (io), 106 D0-DIN-I/O (io), 107 DOUT-I/O (io), 108 CCLK (io), 109 VCC (power), 110 GND (power), 111 A0-~{WSI}-I/O (io), 112 A1-CS2-I/O (io), 113 I/O (io), 114 I/O (io), 115 A2-I/O (io), 116 A3-I/O (io), 117 I/O (io), 118 I/O (io), 119 A15-I/O (io), 120 A4-I/O (io), 121 NC, 122 NC, 123 A14-I/O (io), 124 A5-I/O (io), 125 NC, 126 GND (power), 127 VCC (power), 128 A13-I/O (io), 129 A6-I/O (io), 130 NC, 131 NC, 132 NC, 133 A12-I/O (io), 134 A7-I/O (io), 135 I/O (io), 136 I/O (io), 137 A11-I/O (io), 138 A8-I/O (io), 139 I/O (io), 140 I/O (io), 141 A10-I/O (io), 142 A9-I/O (io), 143 VCC (power), 144 GND (power)

## XC3142A-5CB100B
designator U?
Logic Cell Array with 144 CLBs, with 64 I/O Pins, 100-Pin CQFP, Military Class B Grade; ComponentAvailability: Not for New Design
footprint CB100_N (CQFP, 100-Leads, Body 19x19mm; Pitch 0.635mm, Gullwing Leadform, IPC Medium Density)
footprint CB100_L (CQFP, 100-Leads, Body 19x19mm; Pitch 0.635mm, Gullwing Leadform, IPC High Density)
footprint CB100_M (CQFP, 100-Leads, Body 19x19mm; Pitch 0.635mm, Gullwing Leadform, IPC Low Density)
3D model XC3142A-CB100 (100-Pin Ceramic Brazed Quad Flat Pack (CB100))
pins: 1 GND (power), 2 A13-I/O (io), 3 A6-I/O (io), 4 A12-I/O (io), 5 A7-I/O (io), 6 NC, 7 NC, 8 A11-I/O (io), 9 A8-I/O (io), 10 A10-I/O (io), 11 A9-I/O (io), 12 NC, 13 NC, 14 ~{PWRDN} (in), 15 TCKLIN-I/O (io), 16 NC, 17 NC, 18 NC, 19 I/O (io), 20 I/O (io), 21 I/O (io), 22 I/O (io), 23 I/O (io), 24 I/O (io), 25 I/O (io), 26 VCC (power), 27 I/O (io), 28 I/O (io), 29 I/O (io), 30 I/O (io), 31 I/O (io), 32 I/O (io), 33 I/O (io), 34 I/O (io), 35 NC, 36 NC, 37 M1~{-RD} (out), 38 NC, 39 M0-RT (in), 40 NC, 41 M2-I/O (io), 42 HDC-I/O (io), 43 I/O (io), 44 ~{LDC}-I/O (io), 45 NC, 46 NC, 47 I/O (io), 48 I/O (io), 49 I/O (io), 50 ~{INIT}-I/O (io), 51 GND (power), 52 I/O (io), 53 I/O (io), 54 I/O (io), 55 I/O (io), 56 I/O (io), 57 I/O (io), 58 I/O (io), 59 NC, 60 NC, 61 XTAL2-I/O (io), 62 NC, 63 ~{RESET} (in), 64 NC, 65 DONE~{-PROG} (out), 66 D7-I/O (io), 67 XTAL1-I/O (io), 68 D6-I/O (io), 69 NC, 70 NC, 71 I/O (io), 72 D5-I/O (io), 73 ~{CS}0-I/O (io), 74 D4-I/O (io), 75 I/O (io), 76 VCC (power), 77 D3-I/O (io), 78 ~{CS}1-I/O (io), 79 D2-I/O (io), 80 I/O (io), 81 NC, 82 NC, 83 D1-I/O (io), 84 ~{RCLK}-~{BUSY}/RDY-I/O (io), 85 DO-DIN-I/O (io), 86 DOUT-I/O (io), 87 CCLK (io), 88 NC, 89 NC, 90 A0~{-WS}-I/O (io), 91 A1-CS2-I/O (io), 92 NC, 93 A2-I/O (io), 94 A3-I/O (io), 95 NC, 96 NC, 97 A15-I/O (io), 98 A4-I/O (io), 99 A14-I/O (io), 100 A5-I/O (io)

## XC3142A-5CB100M
designator U?
Logic Cell Array with 144 CLBs, with 64 I/O Pins, 100-Pin CQFP, Military Grade; ComponentAvailability: Not for New Design
footprint CB100_N (CQFP, 100-Leads, Body 19x19mm; Pitch 0.635mm, Gullwing Leadform, IPC Medium Density)
footprint CB100_L (CQFP, 100-Leads, Body 19x19mm; Pitch 0.635mm, Gullwing Leadform, IPC High Density)
footprint CB100_M (CQFP, 100-Leads, Body 19x19mm; Pitch 0.635mm, Gullwing Leadform, IPC Low Density)
3D model XC3142A-CB100 (100-Pin Ceramic Brazed Quad Flat Pack (CB100))
pins: 1 GND (power), 2 A13-I/O (io), 3 A6-I/O (io), 4 A12-I/O (io), 5 A7-I/O (io), 6 NC, 7 NC, 8 A11-I/O (io), 9 A8-I/O (io), 10 A10-I/O (io), 11 A9-I/O (io), 12 NC, 13 NC, 14 ~{PWRDN} (in), 15 TCKLIN-I/O (io), 16 NC, 17 NC, 18 NC, 19 I/O (io), 20 I/O (io), 21 I/O (io), 22 I/O (io), 23 I/O (io), 24 I/O (io), 25 I/O (io), 26 VCC (power), 27 I/O (io), 28 I/O (io), 29 I/O (io), 30 I/O (io), 31 I/O (io), 32 I/O (io), 33 I/O (io), 34 I/O (io), 35 NC, 36 NC, 37 M1~{-RD} (out), 38 NC, 39 M0-RT (in), 40 NC, 41 M2-I/O (io), 42 HDC-I/O (io), 43 I/O (io), 44 ~{LDC}-I/O (io), 45 NC, 46 NC, 47 I/O (io), 48 I/O (io), 49 I/O (io), 50 ~{INIT}-I/O (io), 51 GND (power), 52 I/O (io), 53 I/O (io), 54 I/O (io), 55 I/O (io), 56 I/O (io), 57 I/O (io), 58 I/O (io), 59 NC, 60 NC, 61 XTAL2-I/O (io), 62 NC, 63 ~{RESET} (in), 64 NC, 65 DONE~{-PROG} (out), 66 D7-I/O (io), 67 XTAL1-I/O (io), 68 D6-I/O (io), 69 NC, 70 NC, 71 I/O (io), 72 D5-I/O (io), 73 ~{CS}0-I/O (io), 74 D4-I/O (io), 75 I/O (io), 76 VCC (power), 77 D3-I/O (io), 78 ~{CS}1-I/O (io), 79 D2-I/O (io), 80 I/O (io), 81 NC, 82 NC, 83 D1-I/O (io), 84 ~{RCLK}-~{BUSY}/RDY-I/O (io), 85 DO-DIN-I/O (io), 86 DOUT-I/O (io), 87 CCLK (io), 88 NC, 89 NC, 90 A0~{-WS}-I/O (io), 91 A1-CS2-I/O (io), 92 NC, 93 A2-I/O (io), 94 A3-I/O (io), 95 NC, 96 NC, 97 A15-I/O (io), 98 A4-I/O (io), 99 A14-I/O (io), 100 A5-I/O (io)

## XC3142A-5PC84C
designator U?
Logic Cell Array with 144 CLBs, with 64 I/O Pins, 84-Pin PLCC, Commercial Grade; ComponentAvailability: Not for New Design
footprint PC84_N (Leaded Chip Carrier, 84-Leads, Body 29.3x29.3mm, Pitch 1.27mm, IPC Medium Density)
footprint PC84_L (Leaded Chip Carrier, 84-Leads, Body 29.3x29.3mm, Pitch 1.27mm, IPC High Density)
footprint PC84_M (Leaded Chip Carrier, 84-Leads, Body 29.3x29.3mm, Pitch 1.27mm, IPC Low Density)
3D model XC3142A-PC84 (84-Pin Plastic Leaded Chip Carrier (PC84))
pins: 1 GND (power), 2 A13-I/O (io), 3 A6-I/O (io), 4 A12-I/O (io), 5 A7-I/O (io), 6 NC, 7 NC, 8 A11-I/O (io), 9 A8-I/O (io), 10 A10-I/O (io), 11 A9-I/O (io), 12 ~{PWRDN} (in), 13 TCLKIN-I/O (io), 14 NC, 15 I/O (io), 16 I/O (io), 17 I/O (io), 18 I/O (io), 19 I/O (io), 20 I/O (io), 21 I/O (io), 22 VCC (power), 23 I/O (io), 24 I/O (io), 25 I/O (io), 26 I/O (io), 27 I/O (io), 28 I/O (io), 29 I/O (io), 30 I/O (io), 31 M1-~{RDATA} (out), 32 M0-RTRIG (in), 33 M2-I/O (io), 34 HDC-I/O (io), 35 I/O (io), 36 ~{LDC}-I/O (io), 37 I/O (io), 38 NC, 39 I/O (io), 40 I/O (io), 41 NC, 42 ~{INIT}-I/O (io), 43 GND (power), 44 I/O (io), 45 I/O (io), 46 I/O (io), 47 I/O (io), 48 I/O (io), 49 I/O (io), 50 NC, 51 NC, 52 I/O (io), 53 XTL2 (IN)-I/O (io), 54 ~{RESET} (in), 55 DONE-~{PROG} (out), 56 D7-I/O (io), 57 XTL1(OUT)-BCLKIN-I/O (io), 58 D6-I/O (io), 59 I/O (io), 60 D5-I/O (io), 61 ~{CS}0-I/O (io), 62 D4-I/O (io), 63 I/O (io), 64 VCC (power), 65 D3-I/O (io), 66 ~{CS}1-I/O (io), 67 D2-I/O (io), 68 I/O (io), 69 NC, 70 D1-I/O (io), 71 RDY/~{BUSY}-~{RCLK}-I/O (io), 72 DO-DIN-I/O (io), 73 DOUT-I/O (io), 74 CCLK (io), 75 A0-~{WS}-I/O (io), 76 A1-CS2-I/O (io), 77 A2-I/O (io), 78 A3-I/O (io), 79 NC, 80 NC, 81 A15-I/O (io), 82 A4-I/O (io), 83 A14-I/O (io), 84 A5-I/O (io)

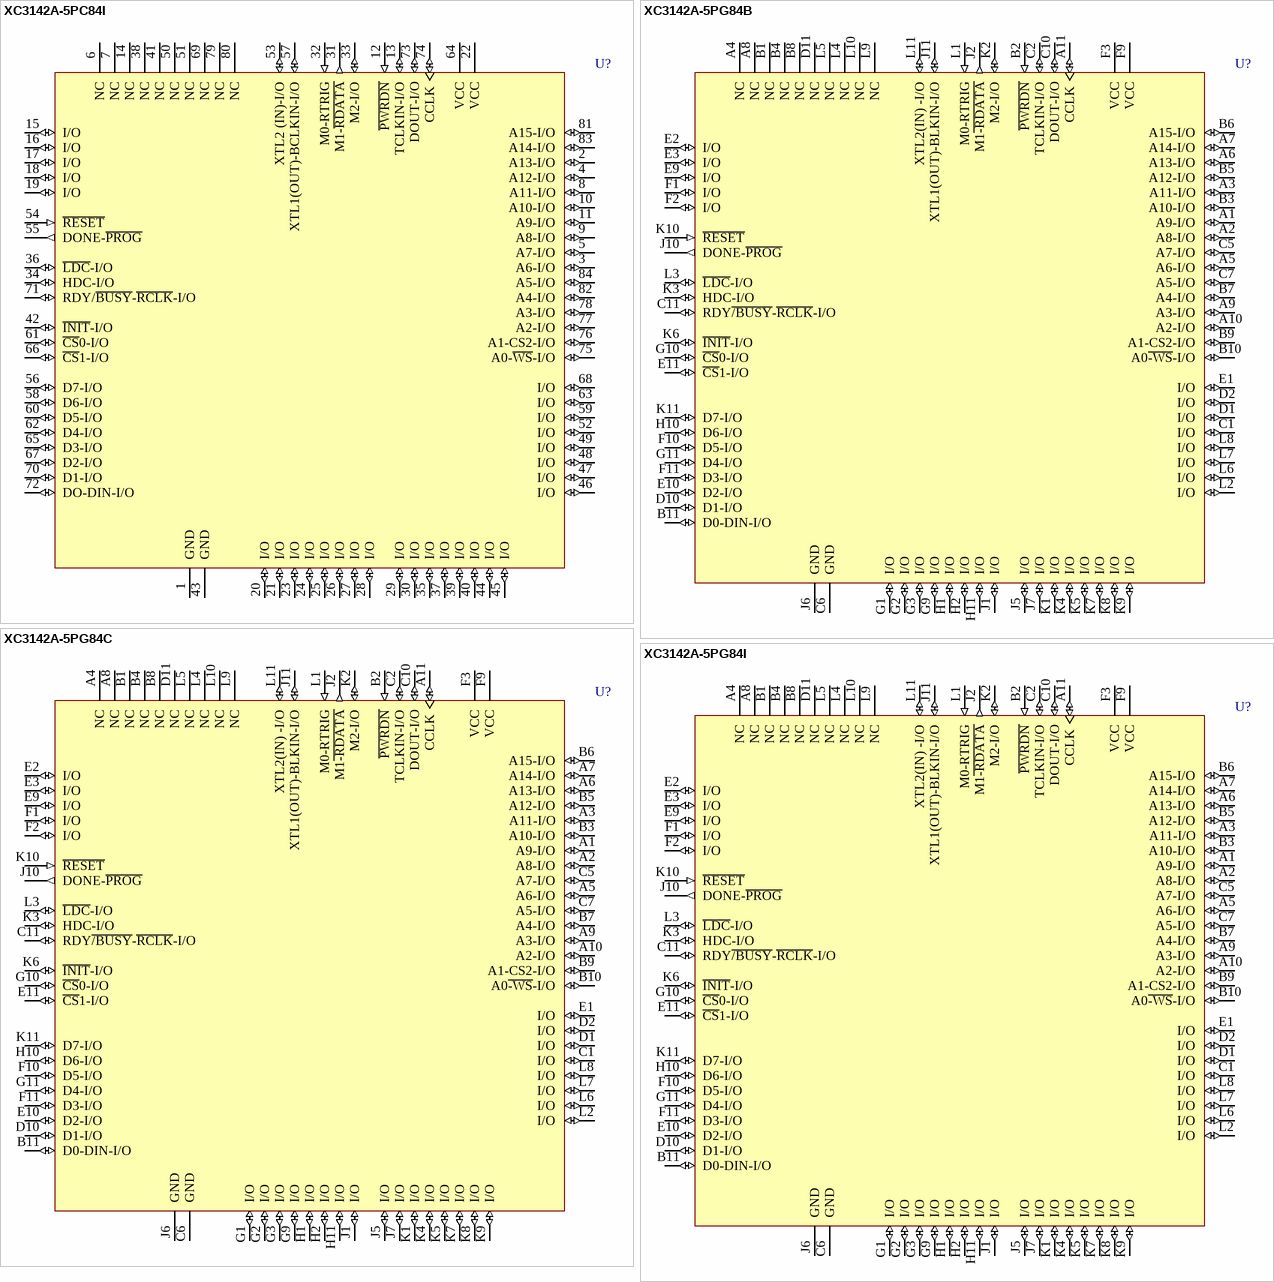
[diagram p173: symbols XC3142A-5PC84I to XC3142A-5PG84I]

## XC3142A-5PC84I
designator U?
Logic Cell Array with 144 CLBs, with 64 I/O Pins, 84-Pin PLCC, Industrial Grade; ComponentAvailability: Not for New Design
footprint PC84_N (Leaded Chip Carrier, 84-Leads, Body 29.3x29.3mm, Pitch 1.27mm, IPC Medium Density)
footprint PC84_L (Leaded Chip Carrier, 84-Leads, Body 29.3x29.3mm, Pitch 1.27mm, IPC High Density)
footprint PC84_M (Leaded Chip Carrier, 84-Leads, Body 29.3x29.3mm, Pitch 1.27mm, IPC Low Density)
3D model XC3142A-PC84 (84-Pin Plastic Leaded Chip Carrier (PC84))
pins: 1 GND (power), 2 A13-I/O (io), 3 A6-I/O (io), 4 A12-I/O (io), 5 A7-I/O (io), 6 NC, 7 NC, 8 A11-I/O (io), 9 A8-I/O (io), 10 A10-I/O (io), 11 A9-I/O (io), 12 ~{PWRDN} (in), 13 TCLKIN-I/O (io), 14 NC, 15 I/O (io), 16 I/O (io), 17 I/O (io), 18 I/O (io), 19 I/O (io), 20 I/O (io), 21 I/O (io), 22 VCC (power), 23 I/O (io), 24 I/O (io), 25 I/O (io), 26 I/O (io), 27 I/O (io), 28 I/O (io), 29 I/O (io), 30 I/O (io), 31 M1-~{RDATA} (out), 32 M0-RTRIG (in), 33 M2-I/O (io), 34 HDC-I/O (io), 35 I/O (io), 36 ~{LDC}-I/O (io), 37 I/O (io), 38 NC, 39 I/O (io), 40 I/O (io), 41 NC, 42 ~{INIT}-I/O (io), 43 GND (power), 44 I/O (io), 45 I/O (io), 46 I/O (io), 47 I/O (io), 48 I/O (io), 49 I/O (io), 50 NC, 51 NC, 52 I/O (io), 53 XTL2 (IN)-I/O (io), 54 ~{RESET} (in), 55 DONE-~{PROG} (out), 56 D7-I/O (io), 57 XTL1(OUT)-BCLKIN-I/O (io), 58 D6-I/O (io), 59 I/O (io), 60 D5-I/O (io), 61 ~{CS}0-I/O (io), 62 D4-I/O (io), 63 I/O (io), 64 VCC (power), 65 D3-I/O (io), 66 ~{CS}1-I/O (io), 67 D2-I/O (io), 68 I/O (io), 69 NC, 70 D1-I/O (io), 71 RDY/~{BUSY}-~{RCLK}-I/O (io), 72 DO-DIN-I/O (io), 73 DOUT-I/O (io), 74 CCLK (io), 75 A0-~{WS}-I/O (io), 76 A1-CS2-I/O (io), 77 A2-I/O (io), 78 A3-I/O (io), 79 NC, 80 NC, 81 A15-I/O (io), 82 A4-I/O (io), 83 A14-I/O (io), 84 A5-I/O (io)

## XC3142A-5PG84B
designator U?
Logic Cell Array with 144 CLBs, with 64 I/O Pins, 84-Pin PGA, Military Class B Grade; ComponentAvailability: Not for New Design
footprint PG84 (PGA, 85-Leads, Body 28x28mm, Pitch 2.54mm)
3D model XC3142A-PG84 (84-Pin Ceramic Pin Grid Array (PG84))
pins: A1 A9-I/O (io), A2 A8-I/O (io), A3 A11-I/O (io), A4 NC, A5 A6-I/O (io), A6 A13-I/O (io), A7 A14-I/O (io), A8 NC, A9 A3-I/O (io), A10 A2-I/O (io), A11 CCLK (io), B1 NC, B2 ~{PWRDN} (in), B3 A10-I/O (io), B4 NC, B5 A12-I/O (io), B6 A15-I/O (io), B7 A4-I/O (io), B8 NC, B9 A1-CS2-I/O (io), B10 A0~{-WS}-I/O (io), B11 D0-DIN-I/O (io), C1 I/O (io), C2 TCLKIN-I/O (io), C5 A7-I/O (io), C6 GND (power), C7 A5-I/O (io), C10 DOUT-I/O (io), C11 RDY~{/BUSY}-~{RCLK}-I/O (io), D1 I/O (io), D2 I/O (io), D10 D1-I/O (io), D11 NC, E1 I/O (io), E2 I/O (io), E3 I/O (io), E9 I/O (io), E10 D2-I/O (io), E11 ~{CS}1-I/O (io), F1 I/O (io), F2 I/O (io), F3 VCC (power), F9 VCC (power), F10 D5-I/O (io), F11 D3-I/O (io), G1 I/O (io), G2 I/O (io), G3 I/O (io), G9 I/O (io), G10 ~{CS}0-I/O (io), G11 D4-I/O (io), H1 I/O (io), H2 I/O (io), H10 D6-I/O (io), H11 I/O (io), J1 I/O (io), J2 M1~{-RDATA} (out), J5 I/O (io), J6 GND (power), J7 I/O (io), J10 DONE-~{PROG} (out), J11 XTL1(OUT)-BLKIN-I/O (io), K1 I/O (io), K2 M2-I/O (io), K3 HDC-I/O (io), K4 I/O (io), K5 I/O (io), K6 ~{INIT}-I/O (io), K7 I/O (io), K8 I/O (io), K9 I/O (io), K10 ~{RESET} (in), K11 D7-I/O (io), L1 M0-RTRIG (in), L2 I/O (io), L3 ~{LDC}-I/O (io), L4 NC, L5 NC, L6 I/O (io), L7 I/O (io), L8 I/O (io), L9 NC, L10 NC, L11 XTL2(IN) -I/O (io)

## XC3142A-5PG84C
designator U?
Logic Cell Array with 144 CLBs, with 64 I/O Pins, 84-Pin PGA, Commercial Grade; ComponentAvailability: Not for New Design
footprint PG84 (PGA, 85-Leads, Body 28x28mm, Pitch 2.54mm)
3D model XC3142A-PG84 (84-Pin Ceramic Pin Grid Array (PG84))
pins: A1 A9-I/O (io), A2 A8-I/O (io), A3 A11-I/O (io), A4 NC, A5 A6-I/O (io), A6 A13-I/O (io), A7 A14-I/O (io), A8 NC, A9 A3-I/O (io), A10 A2-I/O (io), A11 CCLK (io), B1 NC, B2 ~{PWRDN} (in), B3 A10-I/O (io), B4 NC, B5 A12-I/O (io), B6 A15-I/O (io), B7 A4-I/O (io), B8 NC, B9 A1-CS2-I/O (io), B10 A0~{-WS}-I/O (io), B11 D0-DIN-I/O (io), C1 I/O (io), C2 TCLKIN-I/O (io), C5 A7-I/O (io), C6 GND (power), C7 A5-I/O (io), C10 DOUT-I/O (io), C11 RDY~{/BUSY}-~{RCLK}-I/O (io), D1 I/O (io), D2 I/O (io), D10 D1-I/O (io), D11 NC, E1 I/O (io), E2 I/O (io), E3 I/O (io), E9 I/O (io), E10 D2-I/O (io), E11 ~{CS}1-I/O (io), F1 I/O (io), F2 I/O (io), F3 VCC (power), F9 VCC (power), F10 D5-I/O (io), F11 D3-I/O (io), G1 I/O (io), G2 I/O (io), G3 I/O (io), G9 I/O (io), G10 ~{CS}0-I/O (io), G11 D4-I/O (io), H1 I/O (io), H2 I/O (io), H10 D6-I/O (io), H11 I/O (io), J1 I/O (io), J2 M1~{-RDATA} (out), J5 I/O (io), J6 GND (power), J7 I/O (io), J10 DONE-~{PROG} (out), J11 XTL1(OUT)-BLKIN-I/O (io), K1 I/O (io), K2 M2-I/O (io), K3 HDC-I/O (io), K4 I/O (io), K5 I/O (io), K6 ~{INIT}-I/O (io), K7 I/O (io), K8 I/O (io), K9 I/O (io), K10 ~{RESET} (in), K11 D7-I/O (io), L1 M0-RTRIG (in), L2 I/O (io), L3 ~{LDC}-I/O (io), L4 NC, L5 NC, L6 I/O (io), L7 I/O (io), L8 I/O (io), L9 NC, L10 NC, L11 XTL2(IN) -I/O (io)

## XC3142A-5PG84I
designator U?
Logic Cell Array with 144 CLBs, with 64 I/O Pins, 84-Pin PGA, Industrial Grade; ComponentAvailability: Not for New Design
footprint PG84 (PGA, 85-Leads, Body 28x28mm, Pitch 2.54mm)
3D model XC3142A-PG84 (84-Pin Ceramic Pin Grid Array (PG84))
pins: A1 A9-I/O (io), A2 A8-I/O (io), A3 A11-I/O (io), A4 NC, A5 A6-I/O (io), A6 A13-I/O (io), A7 A14-I/O (io), A8 NC, A9 A3-I/O (io), A10 A2-I/O (io), A11 CCLK (io), B1 NC, B2 ~{PWRDN} (in), B3 A10-I/O (io), B4 NC, B5 A12-I/O (io), B6 A15-I/O (io), B7 A4-I/O (io), B8 NC, B9 A1-CS2-I/O (io), B10 A0~{-WS}-I/O (io), B11 D0-DIN-I/O (io), C1 I/O (io), C2 TCLKIN-I/O (io), C5 A7-I/O (io), C6 GND (power), C7 A5-I/O (io), C10 DOUT-I/O (io), C11 RDY~{/BUSY}-~{RCLK}-I/O (io), D1 I/O (io), D2 I/O (io), D10 D1-I/O (io), D11 NC, E1 I/O (io), E2 I/O (io), E3 I/O (io), E9 I/O (io), E10 D2-I/O (io), E11 ~{CS}1-I/O (io), F1 I/O (io), F2 I/O (io), F3 VCC (power), F9 VCC (power), F10 D5-I/O (io), F11 D3-I/O (io), G1 I/O (io), G2 I/O (io), G3 I/O (io), G9 I/O (io), G10 ~{CS}0-I/O (io), G11 D4-I/O (io), H1 I/O (io), H2 I/O (io), H10 D6-I/O (io), H11 I/O (io), J1 I/O (io), J2 M1~{-RDATA} (out), J5 I/O (io), J6 GND (power), J7 I/O (io), J10 DONE-~{PROG} (out), J11 XTL1(OUT)-BLKIN-I/O (io), K1 I/O (io), K2 M2-I/O (io), K3 HDC-I/O (io), K4 I/O (io), K5 I/O (io), K6 ~{INIT}-I/O (io), K7 I/O (io), K8 I/O (io), K9 I/O (io), K10 ~{RESET} (in), K11 D7-I/O (io), L1 M0-RTRIG (in), L2 I/O (io), L3 ~{LDC}-I/O (io), L4 NC, L5 NC, L6 I/O (io), L7 I/O (io), L8 I/O (io), L9 NC, L10 NC, L11 XTL2(IN) -I/O (io)

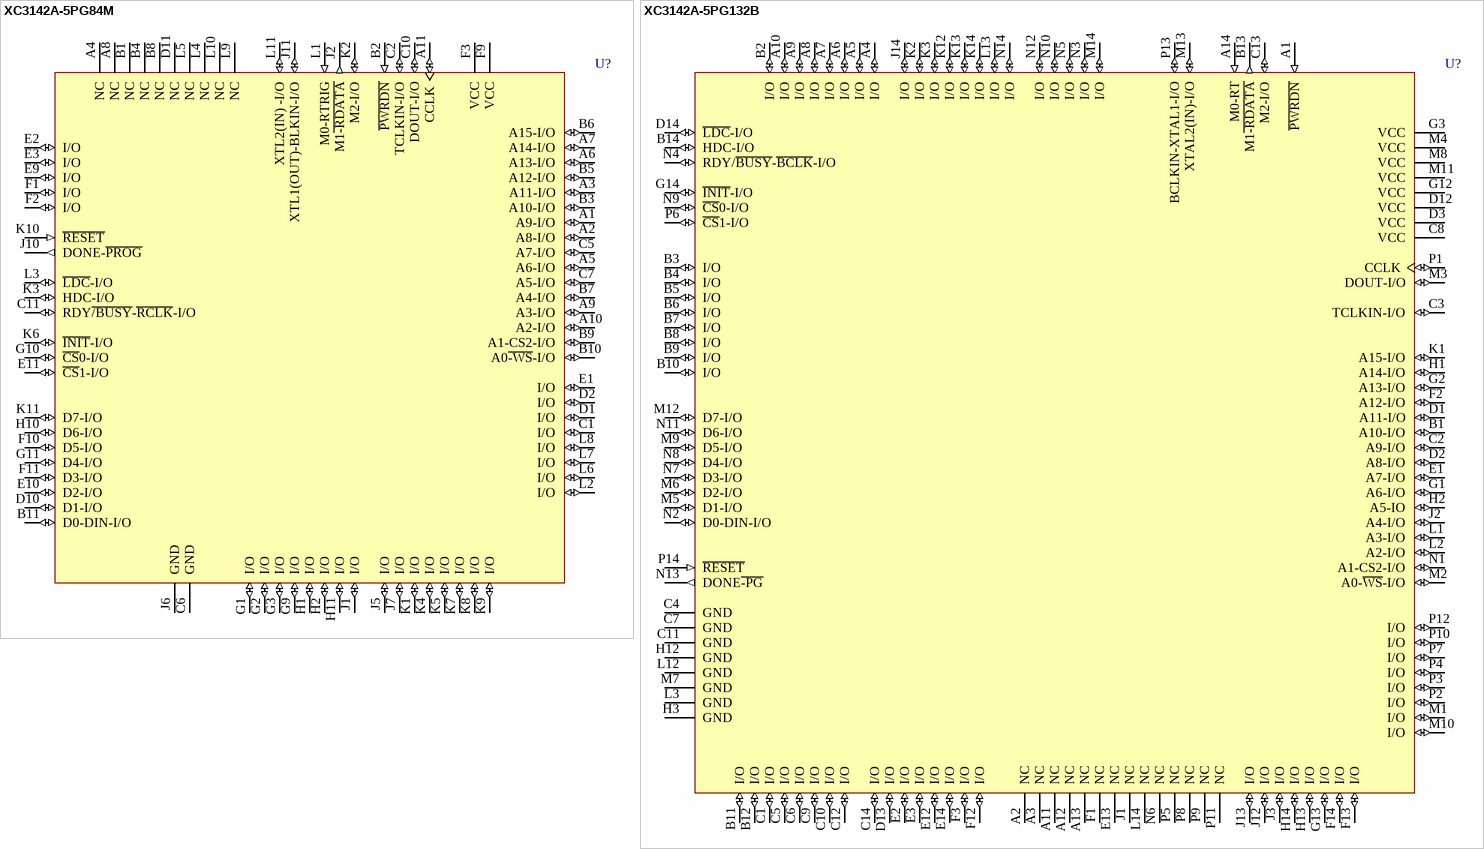
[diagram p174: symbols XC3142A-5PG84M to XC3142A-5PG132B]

## XC3142A-5PG84M
designator U?
Logic Cell Array with 144 CLBs, with 64 I/O Pins, 84-Pin PGA, Military Grade; ComponentAvailability: Not for New Design
footprint PG84 (PGA, 85-Leads, Body 28x28mm, Pitch 2.54mm)
3D model XC3142A-PG84 (84-Pin Ceramic Pin Grid Array (PG84))
pins: A1 A9-I/O (io), A2 A8-I/O (io), A3 A11-I/O (io), A4 NC, A5 A6-I/O (io), A6 A13-I/O (io), A7 A14-I/O (io), A8 NC, A9 A3-I/O (io), A10 A2-I/O (io), A11 CCLK (io), B1 NC, B2 ~{PWRDN} (in), B3 A10-I/O (io), B4 NC, B5 A12-I/O (io), B6 A15-I/O (io), B7 A4-I/O (io), B8 NC, B9 A1-CS2-I/O (io), B10 A0~{-WS}-I/O (io), B11 D0-DIN-I/O (io), C1 I/O (io), C2 TCLKIN-I/O (io), C5 A7-I/O (io), C6 GND (power), C7 A5-I/O (io), C10 DOUT-I/O (io), C11 RDY~{/BUSY}-~{RCLK}-I/O (io), D1 I/O (io), D2 I/O (io), D10 D1-I/O (io), D11 NC, E1 I/O (io), E2 I/O (io), E3 I/O (io), E9 I/O (io), E10 D2-I/O (io), E11 ~{CS}1-I/O (io), F1 I/O (io), F2 I/O (io), F3 VCC (power), F9 VCC (power), F10 D5-I/O (io), F11 D3-I/O (io), G1 I/O (io), G2 I/O (io), G3 I/O (io), G9 I/O (io), G10 ~{CS}0-I/O (io), G11 D4-I/O (io), H1 I/O (io), H2 I/O (io), H10 D6-I/O (io), H11 I/O (io), J1 I/O (io), J2 M1~{-RDATA} (out), J5 I/O (io), J6 GND (power), J7 I/O (io), J10 DONE-~{PROG} (out), J11 XTL1(OUT)-BLKIN-I/O (io), K1 I/O (io), K2 M2-I/O (io), K3 HDC-I/O (io), K4 I/O (io), K5 I/O (io), K6 ~{INIT}-I/O (io), K7 I/O (io), K8 I/O (io), K9 I/O (io), K10 ~{RESET} (in), K11 D7-I/O (io), L1 M0-RTRIG (in), L2 I/O (io), L3 ~{LDC}-I/O (io), L4 NC, L5 NC, L6 I/O (io), L7 I/O (io), L8 I/O (io), L9 NC, L10 NC, L11 XTL2(IN) -I/O (io)

## XC3142A-5PG132B
designator U?
Logic Cell Array with 144 CLBs, with 96 I/O Pins, 132-Pin PGA, Military Class B Grade; ComponentAvailability: Not for New Design
footprint PG132 (PGA, 132-Leads, Body 37x37mm, Pitch 2.54mm)
3D model XC3142A-PG132 (132-Pin Ceramic Pin Grid Array (PG132))
pins: A1 ~{PWRDN} (in), A2 NC, A3 NC, A4 I/O (io), A5 I/O (io), A6 I/O (io), A7 I/O (io), A8 I/O (io), A9 I/O (io), A10 I/O (io), A11 NC, A12 NC, A13 NC, A14 M0-RT (in), B1 A10-I/O (io), B2 I/O (io), B3 I/O (io), B4 I/O (io), B5 I/O (io), B6 I/O (io), B7 I/O (io), B8 I/O (io), B9 I/O (io), B10 I/O (io), B11 I/O (io), B12 I/O (io), B13 M1~{-RDATA} (out), B14 HDC-I/O (io), C1 I/O (io), C2 A9-I/O (io), C3 TCLKIN-I/O (io), C4 GND (power), C5 I/O (io), C6 I/O (io), C7 GND (power), C8 VCC (power), C9 I/O (io), C10 I/O (io), C11 GND (power), C12 I/O (io), C13 M2-I/O (io), C14 I/O (io), D1 A11-I/O (io), D2 A8-I/O (io), D3 VCC (power), D12 VCC (power), D13 I/O (io), D14 ~{LDC}-I/O (io), E1 A7-I/O (io), E2 I/O (io), E3 I/O (io), E12 I/O (io), E13 NC, E14 I/O (io), F1 NC, F2 A12-I/O (io), F3 I/O (io), F12 I/O (io), F13 I/O (io), F14 I/O (io), G1 A6-I/O (io), G2 A13-I/O (io), G3 VCC (power), G12 VCC (power), G13 I/O (io), G14 ~{INIT}-I/O (io), H1 A14-I/O (io), H2 A5-IO (io), H3 GND (power), H12 GND (power), H13 I/O (io), H14 I/O (io), J1 NC, J2 A4-I/O (io), J3 I/O (io), J12 I/O (io), J13 I/O (io), J14 I/O (io), K1 A15-I/O (io), K2 I/O (io), K3 I/O (io), K12 I/O (io), K13 I/O (io), K14 I/O (io), L1 A3-I/O (io), L2 A2-I/O (io), L3 GND (power), L12 GND (power), L13 I/O (io), L14 NC, M1 I/O (io), M2 A0-~{WS}-I/O (io), M3 DOUT-I/O (io), M4 VCC (power), M5 D1-I/O (io), M6 D2-I/O (io), M7 GND (power), M8 VCC (power), M9 D5-I/O (io), M10 I/O (io), M11 VCC (power), M12 D7-I/O (io), M13 XTAL2(IN)-I/O (io), M14 I/O (io), N1 A1-CS2-I/O (io), N2 D0-DIN-I/O (io), N3 I/O (io), N4 RDY/~{BUSY}-~{BCLK}-I/O (io), N5 I/O (io), N6 NC, N7 D3-I/O (io), N8 D4-I/O (io), N9 ~{CS}0-I/O (io), N10 I/O (io), N11 D6-I/O (io), N12 I/O (io), N13 DONE~{-PG} (out), N14 I/O (io), P1 CCLK (io), P2 I/O (io), P3 I/O (io), P4 I/O (io), P5 NC, P6 ~{CS}1-I/O (io), P7 I/O (io), P8 NC, P9 NC, P10 I/O (io), P11 NC, P12 I/O (io), P13 BCLKIN-XTAL1-I/O (io), P14 ~{RESET} (in)

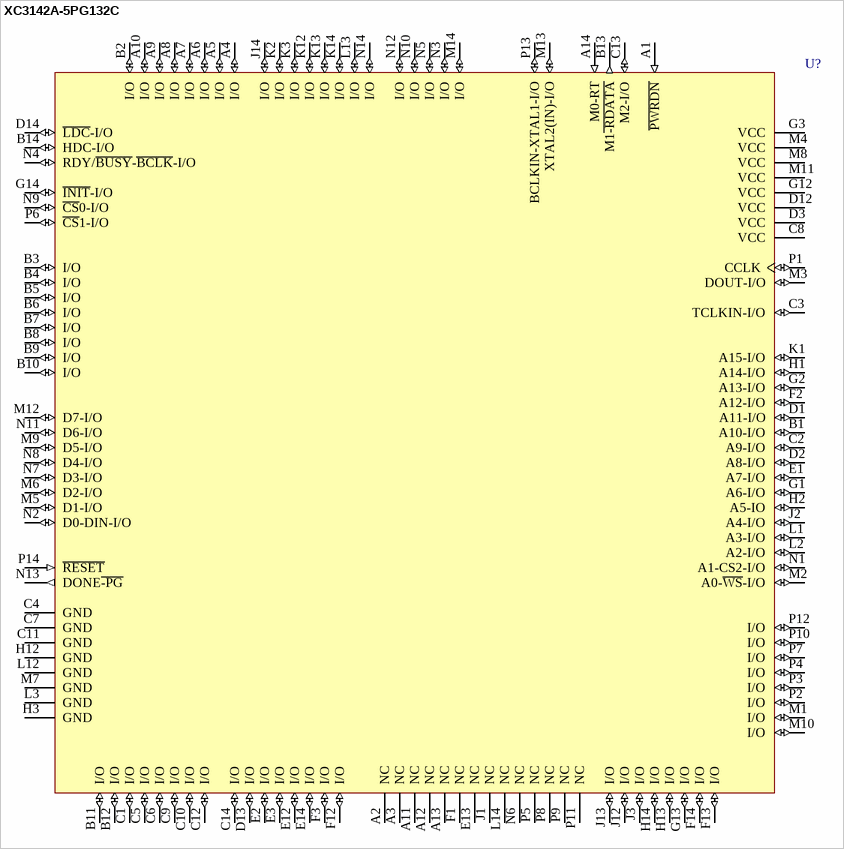
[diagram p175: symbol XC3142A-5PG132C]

## XC3142A-5PG132C
designator U?
Logic Cell Array with 144 CLBs, with 96 I/O Pins, 132-Pin PGA, Commercial Grade; ComponentAvailability: Not for New Design
footprint PG132 (PGA, 132-Leads, Body 37x37mm, Pitch 2.54mm)
3D model XC3142A-PG132 (132-Pin Ceramic Pin Grid Array (PG132))
pins: A1 ~{PWRDN} (in), A2 NC, A3 NC, A4 I/O (io), A5 I/O (io), A6 I/O (io), A7 I/O (io), A8 I/O (io), A9 I/O (io), A10 I/O (io), A11 NC, A12 NC, A13 NC, A14 M0-RT (in), B1 A10-I/O (io), B2 I/O (io), B3 I/O (io), B4 I/O (io), B5 I/O (io), B6 I/O (io), B7 I/O (io), B8 I/O (io), B9 I/O (io), B10 I/O (io), B11 I/O (io), B12 I/O (io), B13 M1~{-RDATA} (out), B14 HDC-I/O (io), C1 I/O (io), C2 A9-I/O (io), C3 TCLKIN-I/O (io), C4 GND (power), C5 I/O (io), C6 I/O (io), C7 GND (power), C8 VCC (power), C9 I/O (io), C10 I/O (io), C11 GND (power), C12 I/O (io), C13 M2-I/O (io), C14 I/O (io), D1 A11-I/O (io), D2 A8-I/O (io), D3 VCC (power), D12 VCC (power), D13 I/O (io), D14 ~{LDC}-I/O (io), E1 A7-I/O (io), E2 I/O (io), E3 I/O (io), E12 I/O (io), E13 NC, E14 I/O (io), F1 NC, F2 A12-I/O (io), F3 I/O (io), F12 I/O (io), F13 I/O (io), F14 I/O (io), G1 A6-I/O (io), G2 A13-I/O (io), G3 VCC (power), G12 VCC (power), G13 I/O (io), G14 ~{INIT}-I/O (io), H1 A14-I/O (io), H2 A5-IO (io), H3 GND (power), H12 GND (power), H13 I/O (io), H14 I/O (io), J1 NC, J2 A4-I/O (io), J3 I/O (io), J12 I/O (io), J13 I/O (io), J14 I/O (io), K1 A15-I/O (io), K2 I/O (io), K3 I/O (io), K12 I/O (io), K13 I/O (io), K14 I/O (io), L1 A3-I/O (io), L2 A2-I/O (io), L3 GND (power), L12 GND (power), L13 I/O (io), L14 NC, M1 I/O (io), M2 A0-~{WS}-I/O (io), M3 DOUT-I/O (io), M4 VCC (power), M5 D1-I/O (io), M6 D2-I/O (io), M7 GND (power), M8 VCC (power), M9 D5-I/O (io), M10 I/O (io), M11 VCC (power), M12 D7-I/O (io), M13 XTAL2(IN)-I/O (io), M14 I/O (io), N1 A1-CS2-I/O (io), N2 D0-DIN-I/O (io), N3 I/O (io), N4 RDY/~{BUSY}-~{BCLK}-I/O (io), N5 I/O (io), N6 NC, N7 D3-I/O (io), N8 D4-I/O (io), N9 ~{CS}0-I/O (io), N10 I/O (io), N11 D6-I/O (io), N12 I/O (io), N13 DONE~{-PG} (out), N14 I/O (io), P1 CCLK (io), P2 I/O (io), P3 I/O (io), P4 I/O (io), P5 NC, P6 ~{CS}1-I/O (io), P7 I/O (io), P8 NC, P9 NC, P10 I/O (io), P11 NC, P12 I/O (io), P13 BCLKIN-XTAL1-I/O (io), P14 ~{RESET} (in)

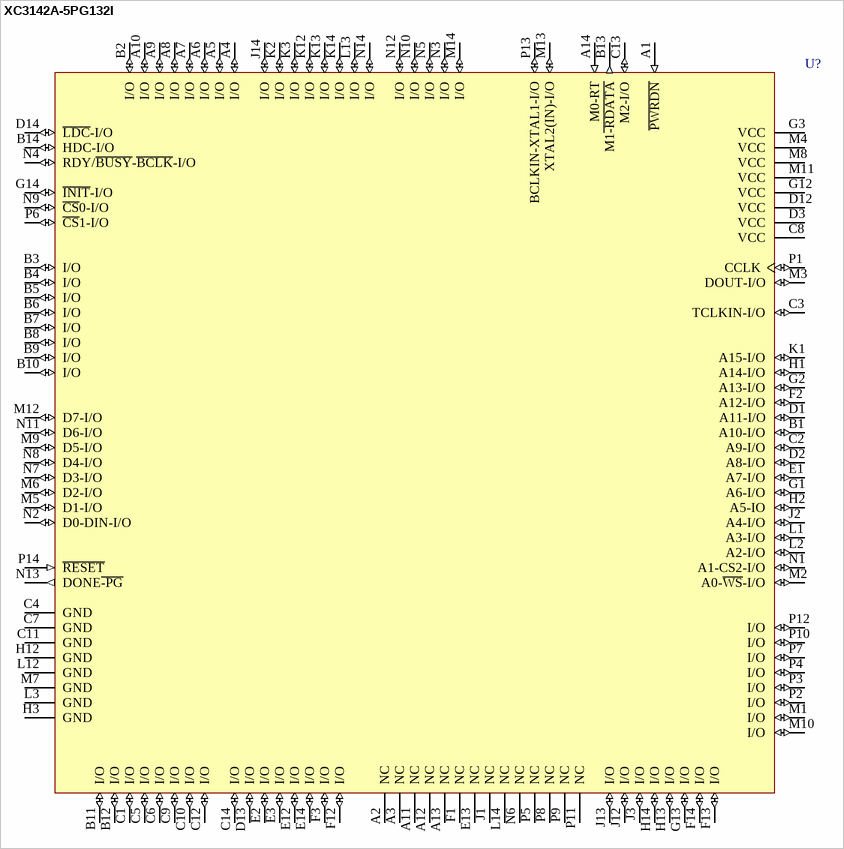
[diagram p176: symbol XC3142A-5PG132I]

## XC3142A-5PG132I
designator U?
Logic Cell Array with 144 CLBs, with 96 I/O Pins, 132-Pin PGA, Industrial Grade; ComponentAvailability: Not for New Design
footprint PG132 (PGA, 132-Leads, Body 37x37mm, Pitch 2.54mm)
3D model XC3142A-PG132 (132-Pin Ceramic Pin Grid Array (PG132))
pins: A1 ~{PWRDN} (in), A2 NC, A3 NC, A4 I/O (io), A5 I/O (io), A6 I/O (io), A7 I/O (io), A8 I/O (io), A9 I/O (io), A10 I/O (io), A11 NC, A12 NC, A13 NC, A14 M0-RT (in), B1 A10-I/O (io), B2 I/O (io), B3 I/O (io), B4 I/O (io), B5 I/O (io), B6 I/O (io), B7 I/O (io), B8 I/O (io), B9 I/O (io), B10 I/O (io), B11 I/O (io), B12 I/O (io), B13 M1~{-RDATA} (out), B14 HDC-I/O (io), C1 I/O (io), C2 A9-I/O (io), C3 TCLKIN-I/O (io), C4 GND (power), C5 I/O (io), C6 I/O (io), C7 GND (power), C8 VCC (power), C9 I/O (io), C10 I/O (io), C11 GND (power), C12 I/O (io), C13 M2-I/O (io), C14 I/O (io), D1 A11-I/O (io), D2 A8-I/O (io), D3 VCC (power), D12 VCC (power), D13 I/O (io), D14 ~{LDC}-I/O (io), E1 A7-I/O (io), E2 I/O (io), E3 I/O (io), E12 I/O (io), E13 NC, E14 I/O (io), F1 NC, F2 A12-I/O (io), F3 I/O (io), F12 I/O (io), F13 I/O (io), F14 I/O (io), G1 A6-I/O (io), G2 A13-I/O (io), G3 VCC (power), G12 VCC (power), G13 I/O (io), G14 ~{INIT}-I/O (io), H1 A14-I/O (io), H2 A5-IO (io), H3 GND (power), H12 GND (power), H13 I/O (io), H14 I/O (io), J1 NC, J2 A4-I/O (io), J3 I/O (io), J12 I/O (io), J13 I/O (io), J14 I/O (io), K1 A15-I/O (io), K2 I/O (io), K3 I/O (io), K12 I/O (io), K13 I/O (io), K14 I/O (io), L1 A3-I/O (io), L2 A2-I/O (io), L3 GND (power), L12 GND (power), L13 I/O (io), L14 NC, M1 I/O (io), M2 A0-~{WS}-I/O (io), M3 DOUT-I/O (io), M4 VCC (power), M5 D1-I/O (io), M6 D2-I/O (io), M7 GND (power), M8 VCC (power), M9 D5-I/O (io), M10 I/O (io), M11 VCC (power), M12 D7-I/O (io), M13 XTAL2(IN)-I/O (io), M14 I/O (io), N1 A1-CS2-I/O (io), N2 D0-DIN-I/O (io), N3 I/O (io), N4 RDY/~{BUSY}-~{BCLK}-I/O (io), N5 I/O (io), N6 NC, N7 D3-I/O (io), N8 D4-I/O (io), N9 ~{CS}0-I/O (io), N10 I/O (io), N11 D6-I/O (io), N12 I/O (io), N13 DONE~{-PG} (out), N14 I/O (io), P1 CCLK (io), P2 I/O (io), P3 I/O (io), P4 I/O (io), P5 NC, P6 ~{CS}1-I/O (io), P7 I/O (io), P8 NC, P9 NC, P10 I/O (io), P11 NC, P12 I/O (io), P13 BCLKIN-XTAL1-I/O (io), P14 ~{RESET} (in)

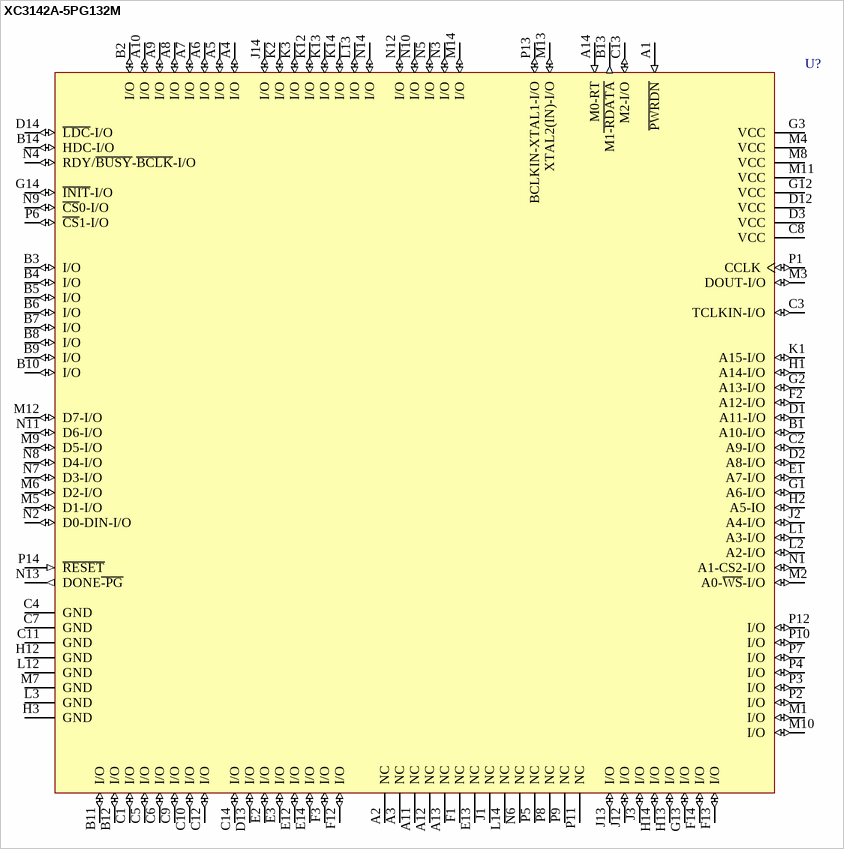
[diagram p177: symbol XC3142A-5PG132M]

## XC3142A-5PG132M
designator U?
Logic Cell Array with 144 CLBs, with 96 I/O Pins, 132-Pin PGA, Military Grade; ComponentAvailability: Not for New Design
footprint PG132 (PGA, 132-Leads, Body 37x37mm, Pitch 2.54mm)
3D model XC3142A-PG132 (132-Pin Ceramic Pin Grid Array (PG132))
pins: A1 ~{PWRDN} (in), A2 NC, A3 NC, A4 I/O (io), A5 I/O (io), A6 I/O (io), A7 I/O (io), A8 I/O (io), A9 I/O (io), A10 I/O (io), A11 NC, A12 NC, A13 NC, A14 M0-RT (in), B1 A10-I/O (io), B2 I/O (io), B3 I/O (io), B4 I/O (io), B5 I/O (io), B6 I/O (io), B7 I/O (io), B8 I/O (io), B9 I/O (io), B10 I/O (io), B11 I/O (io), B12 I/O (io), B13 M1~{-RDATA} (out), B14 HDC-I/O (io), C1 I/O (io), C2 A9-I/O (io), C3 TCLKIN-I/O (io), C4 GND (power), C5 I/O (io), C6 I/O (io), C7 GND (power), C8 VCC (power), C9 I/O (io), C10 I/O (io), C11 GND (power), C12 I/O (io), C13 M2-I/O (io), C14 I/O (io), D1 A11-I/O (io), D2 A8-I/O (io), D3 VCC (power), D12 VCC (power), D13 I/O (io), D14 ~{LDC}-I/O (io), E1 A7-I/O (io), E2 I/O (io), E3 I/O (io), E12 I/O (io), E13 NC, E14 I/O (io), F1 NC, F2 A12-I/O (io), F3 I/O (io), F12 I/O (io), F13 I/O (io), F14 I/O (io), G1 A6-I/O (io), G2 A13-I/O (io), G3 VCC (power), G12 VCC (power), G13 I/O (io), G14 ~{INIT}-I/O (io), H1 A14-I/O (io), H2 A5-IO (io), H3 GND (power), H12 GND (power), H13 I/O (io), H14 I/O (io), J1 NC, J2 A4-I/O (io), J3 I/O (io), J12 I/O (io), J13 I/O (io), J14 I/O (io), K1 A15-I/O (io), K2 I/O (io), K3 I/O (io), K12 I/O (io), K13 I/O (io), K14 I/O (io), L1 A3-I/O (io), L2 A2-I/O (io), L3 GND (power), L12 GND (power), L13 I/O (io), L14 NC, M1 I/O (io), M2 A0-~{WS}-I/O (io), M3 DOUT-I/O (io), M4 VCC (power), M5 D1-I/O (io), M6 D2-I/O (io), M7 GND (power), M8 VCC (power), M9 D5-I/O (io), M10 I/O (io), M11 VCC (power), M12 D7-I/O (io), M13 XTAL2(IN)-I/O (io), M14 I/O (io), N1 A1-CS2-I/O (io), N2 D0-DIN-I/O (io), N3 I/O (io), N4 RDY/~{BUSY}-~{BCLK}-I/O (io), N5 I/O (io), N6 NC, N7 D3-I/O (io), N8 D4-I/O (io), N9 ~{CS}0-I/O (io), N10 I/O (io), N11 D6-I/O (io), N12 I/O (io), N13 DONE~{-PG} (out), N14 I/O (io), P1 CCLK (io), P2 I/O (io), P3 I/O (io), P4 I/O (io), P5 NC, P6 ~{CS}1-I/O (io), P7 I/O (io), P8 NC, P9 NC, P10 I/O (io), P11 NC, P12 I/O (io), P13 BCLKIN-XTAL1-I/O (io), P14 ~{RESET} (in)

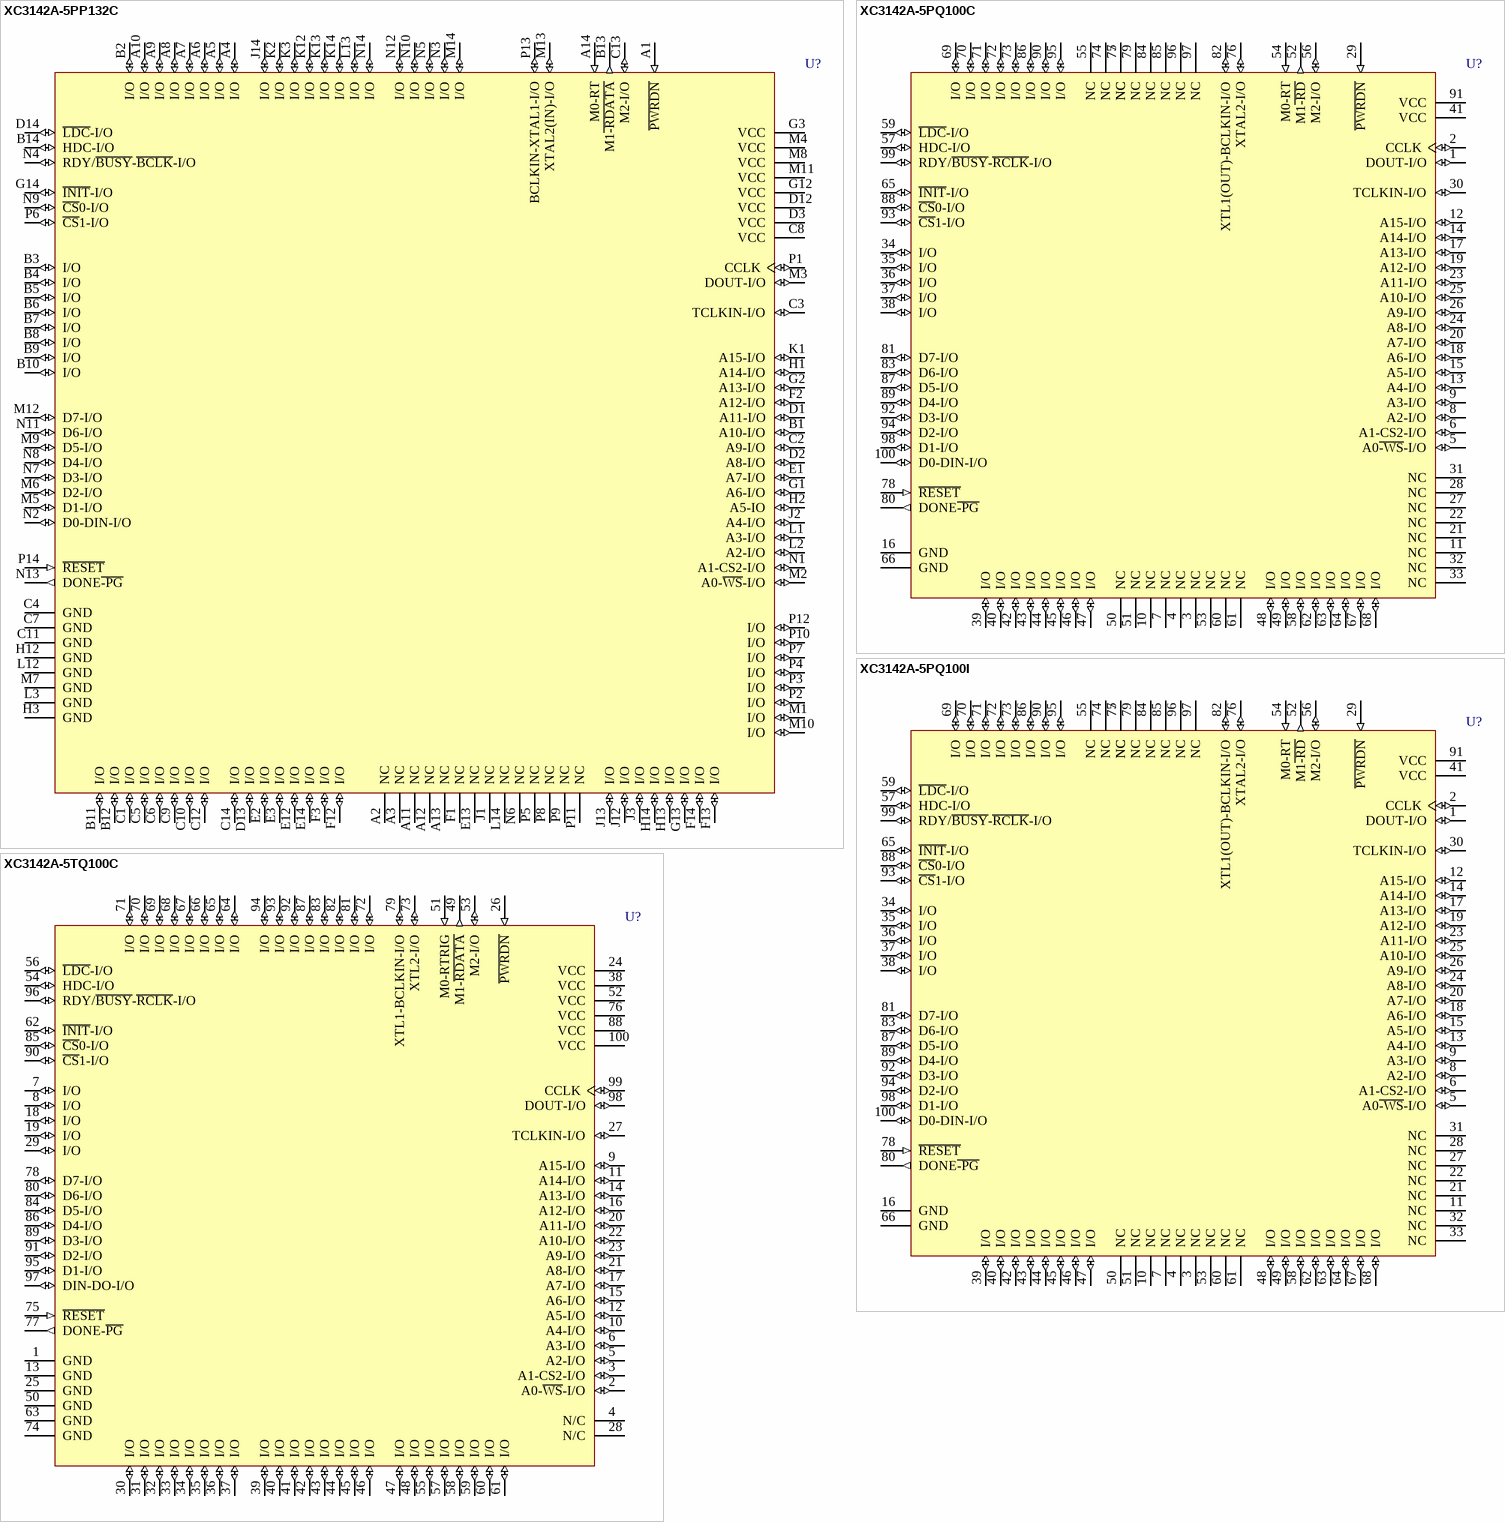
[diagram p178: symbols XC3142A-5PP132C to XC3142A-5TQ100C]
